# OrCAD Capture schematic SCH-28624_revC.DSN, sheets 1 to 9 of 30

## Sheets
1 19 XG-T PHY 2 Pwr: size B; title: T1024RDB; rev: C
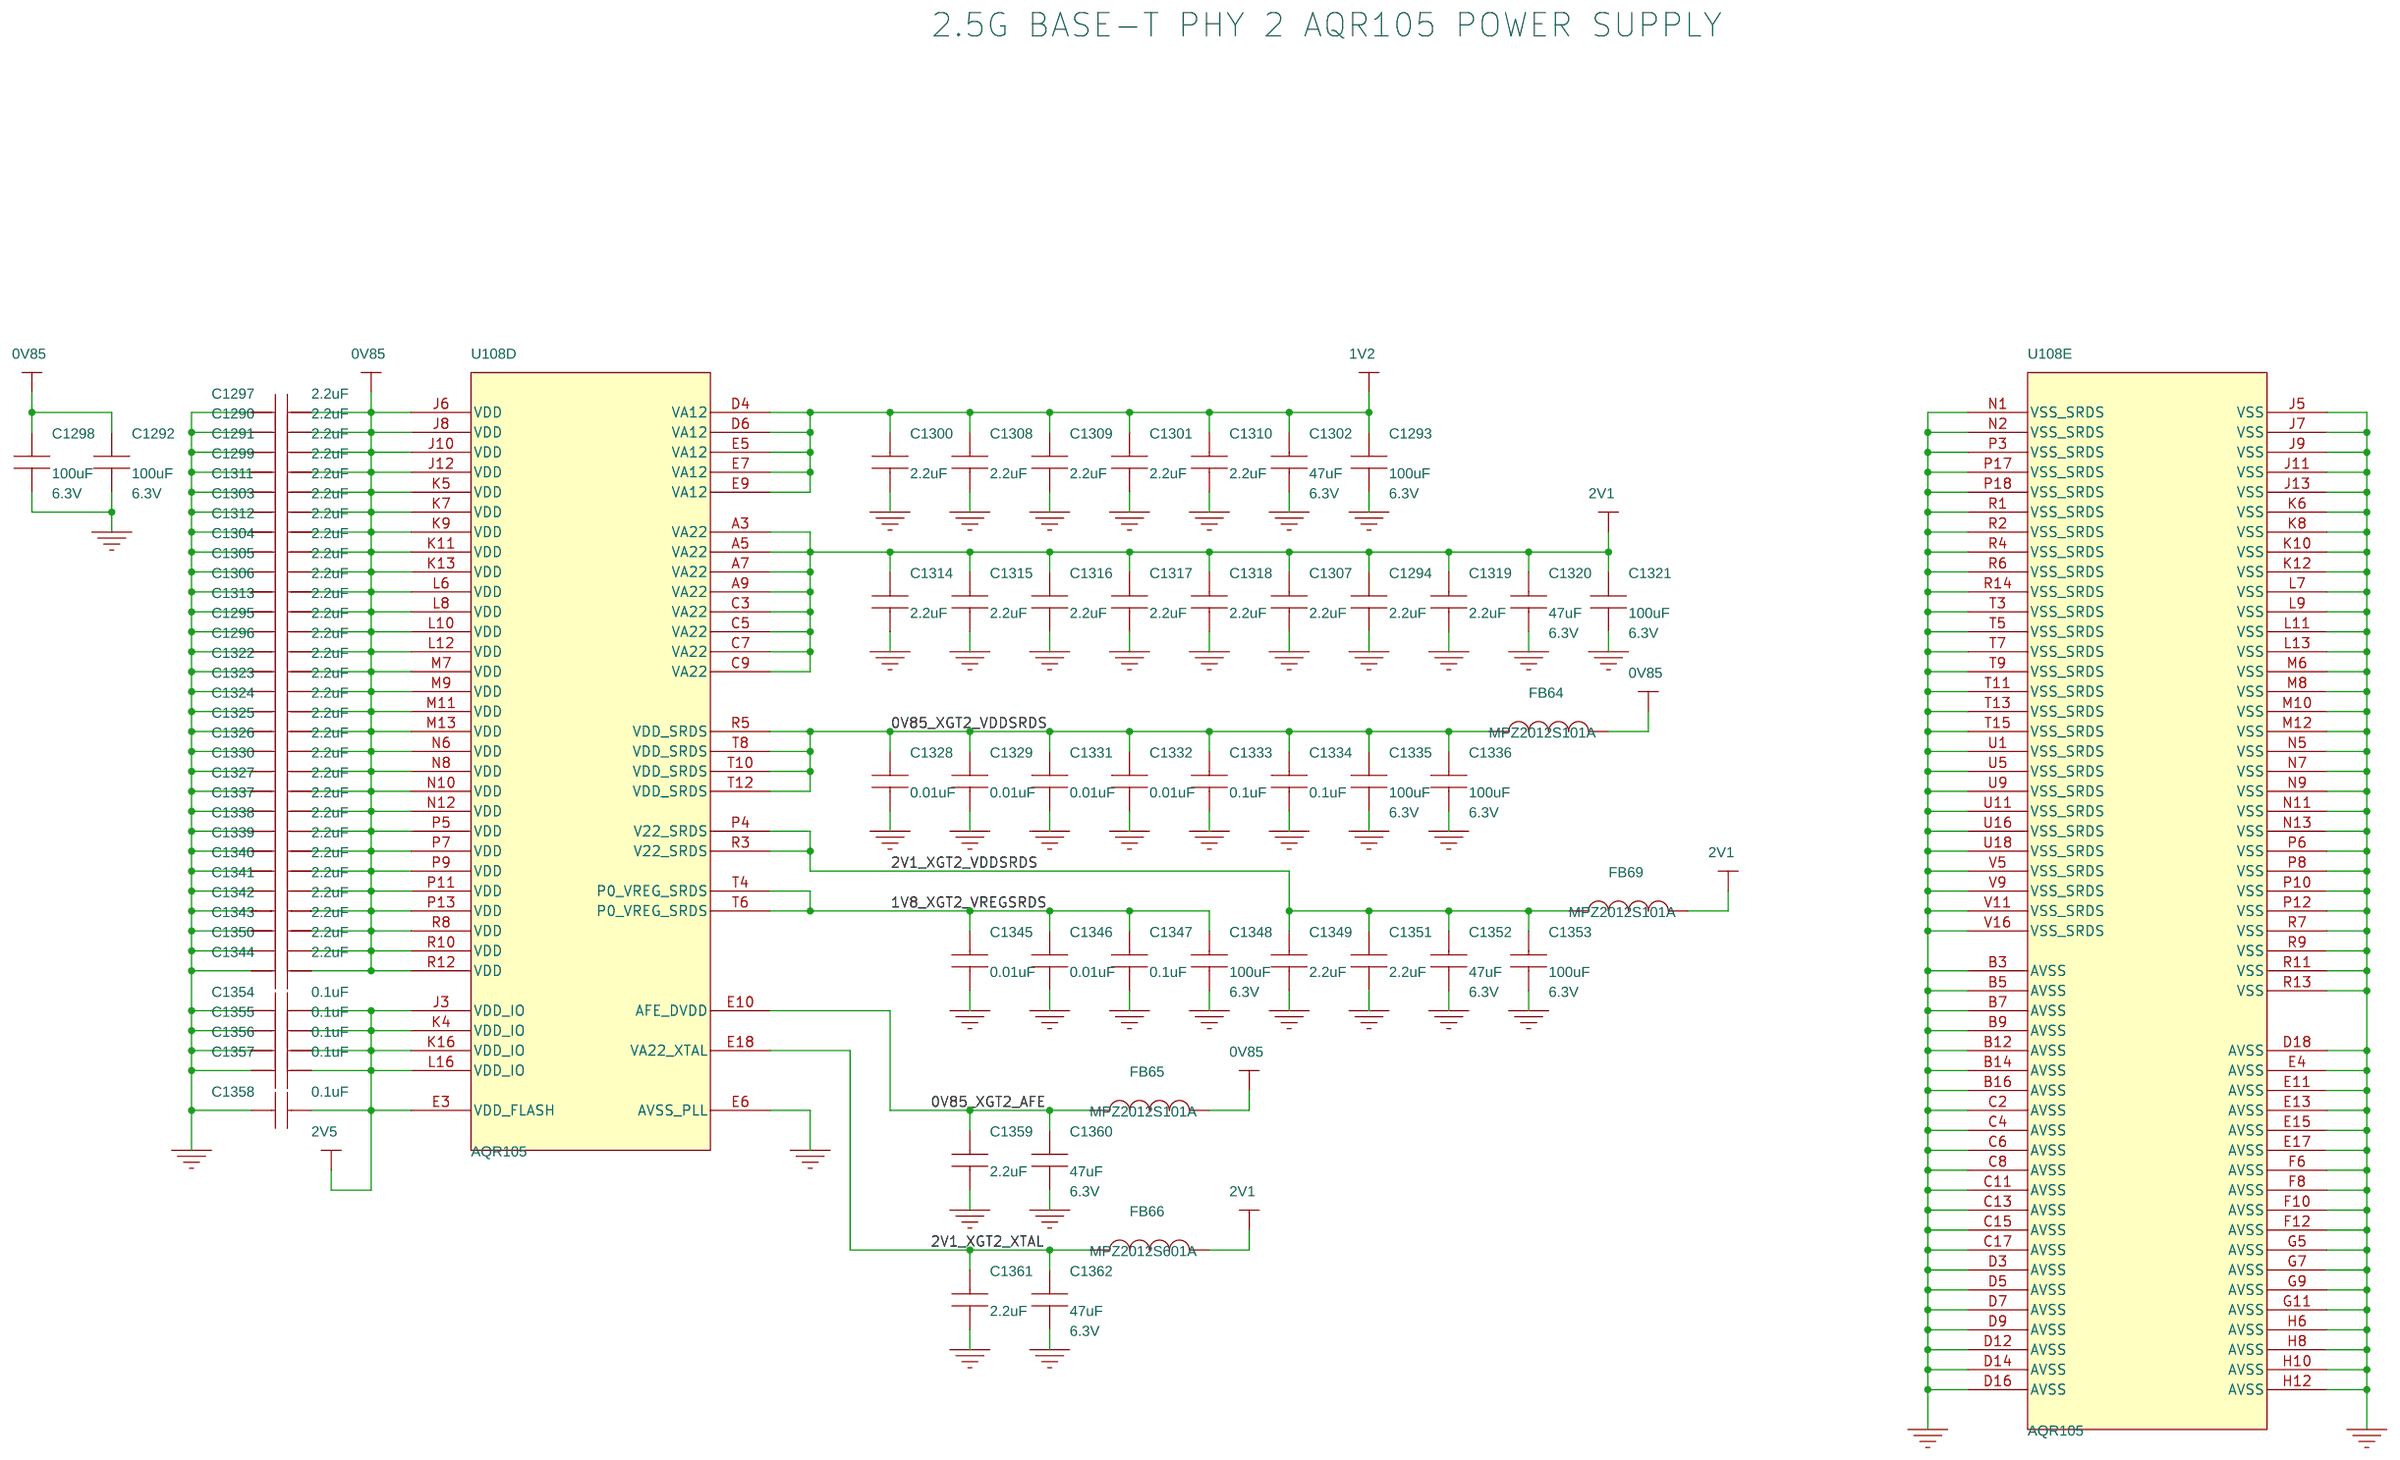
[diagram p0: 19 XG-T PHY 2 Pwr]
2 18 XG-T PHY 2: size B
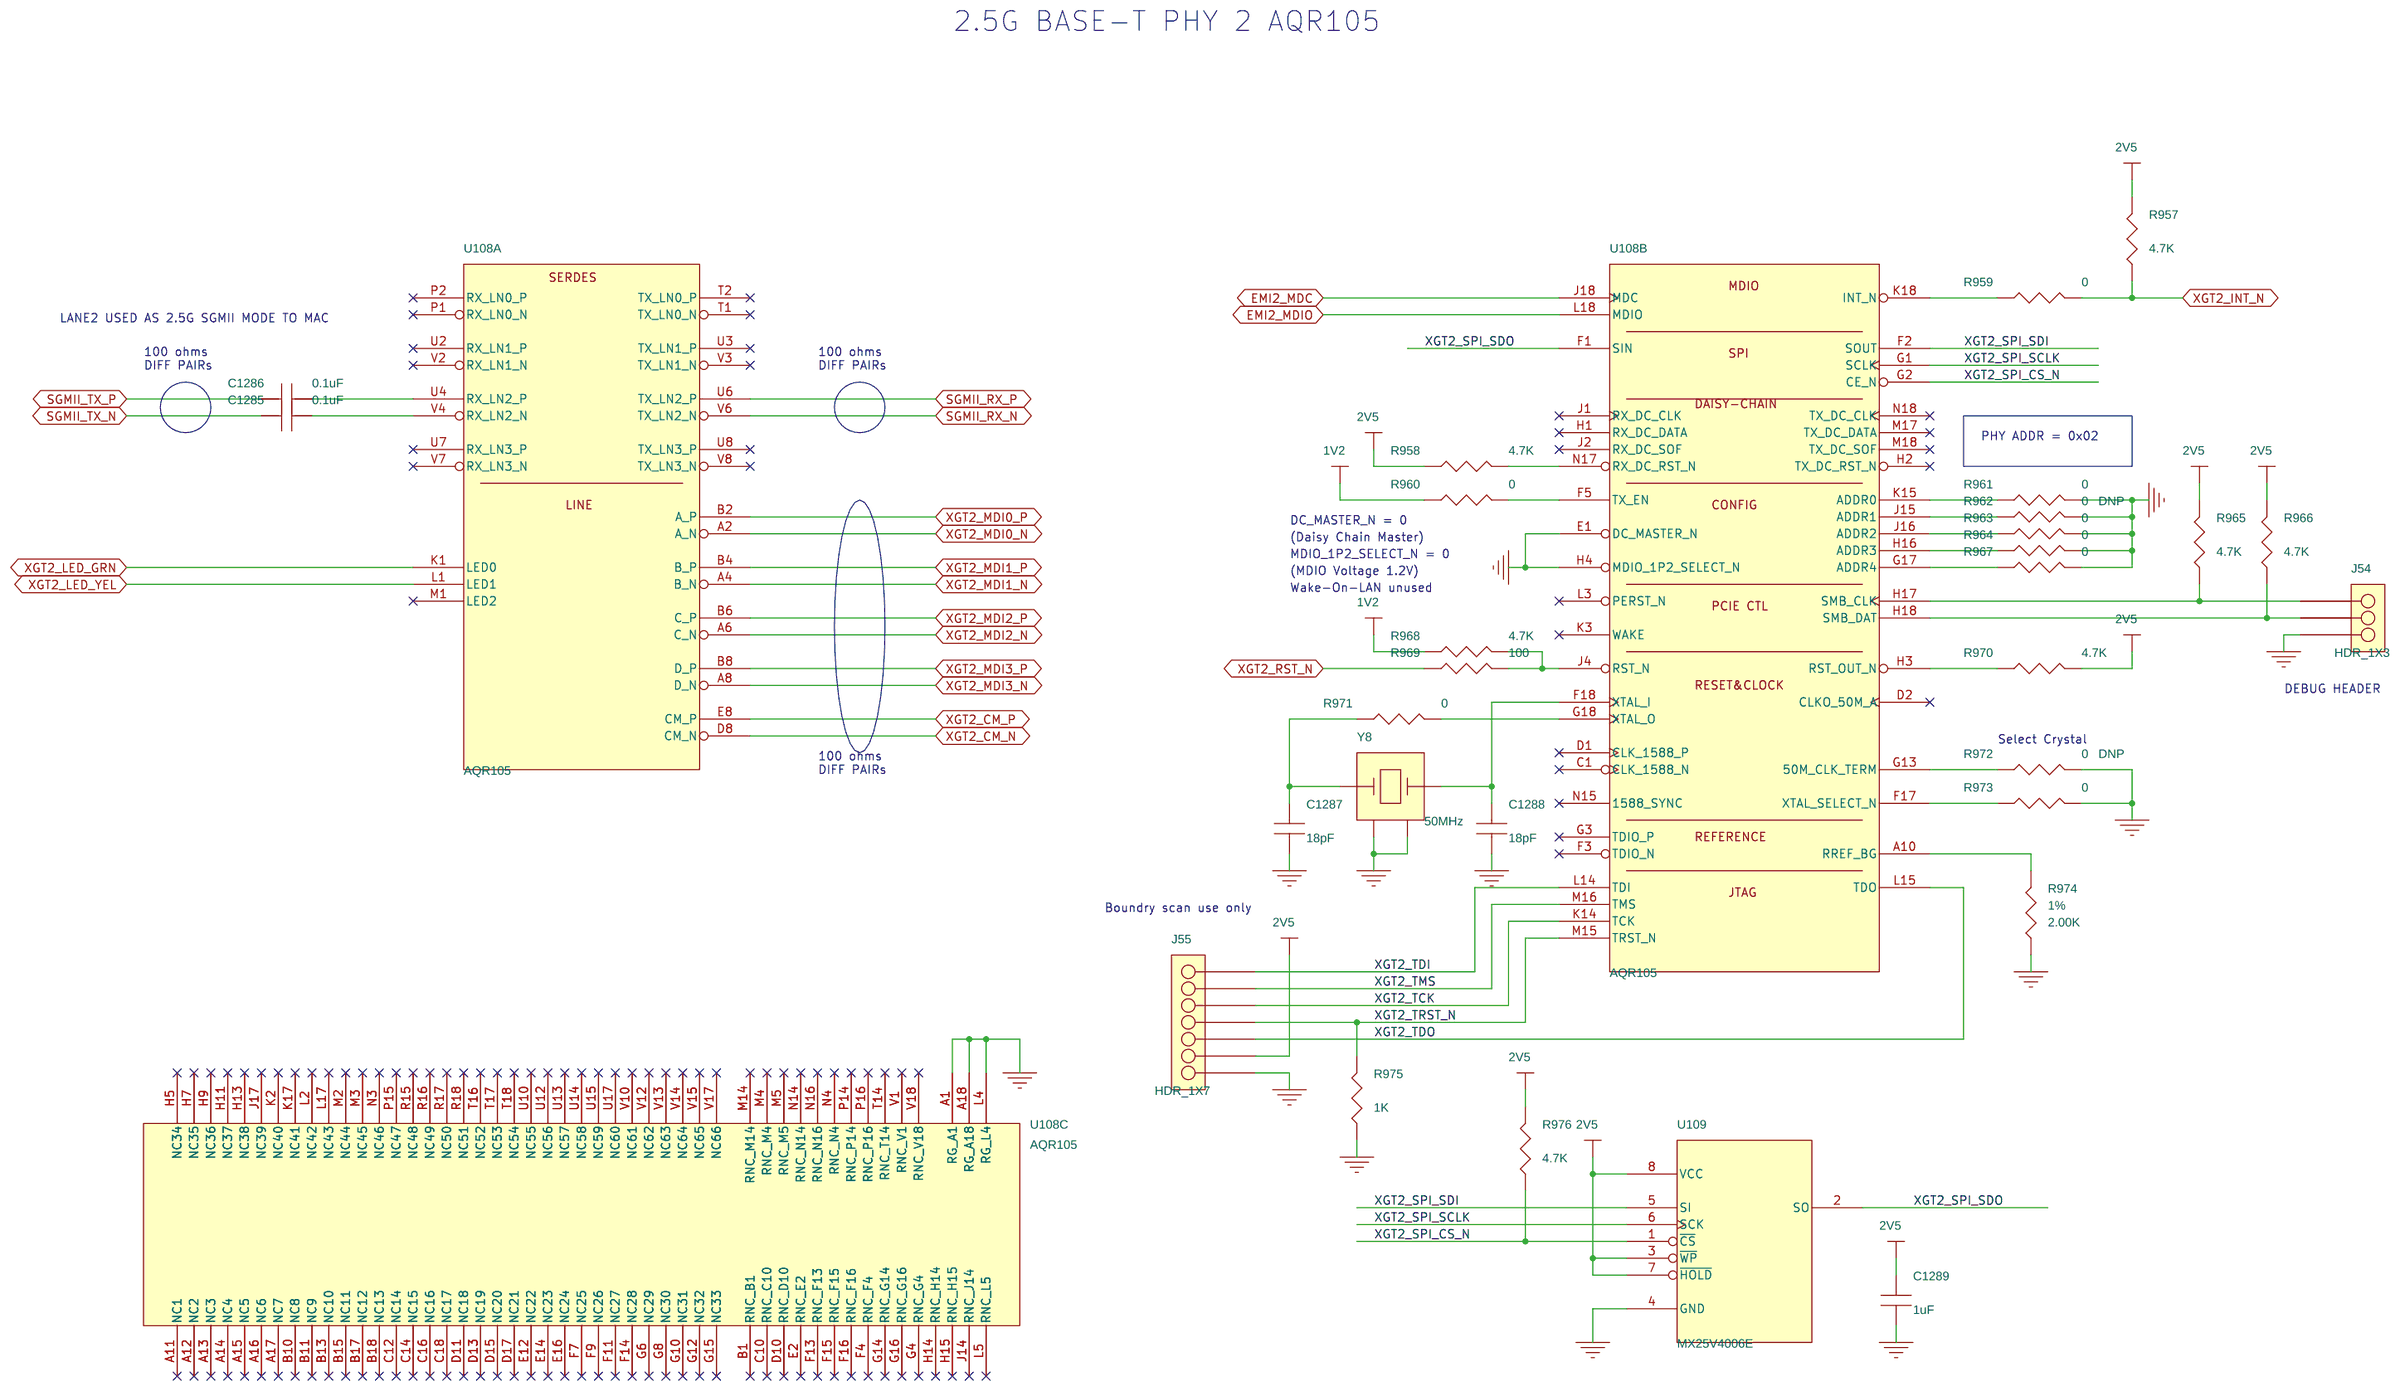
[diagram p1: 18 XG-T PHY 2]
3 01 Page Listing
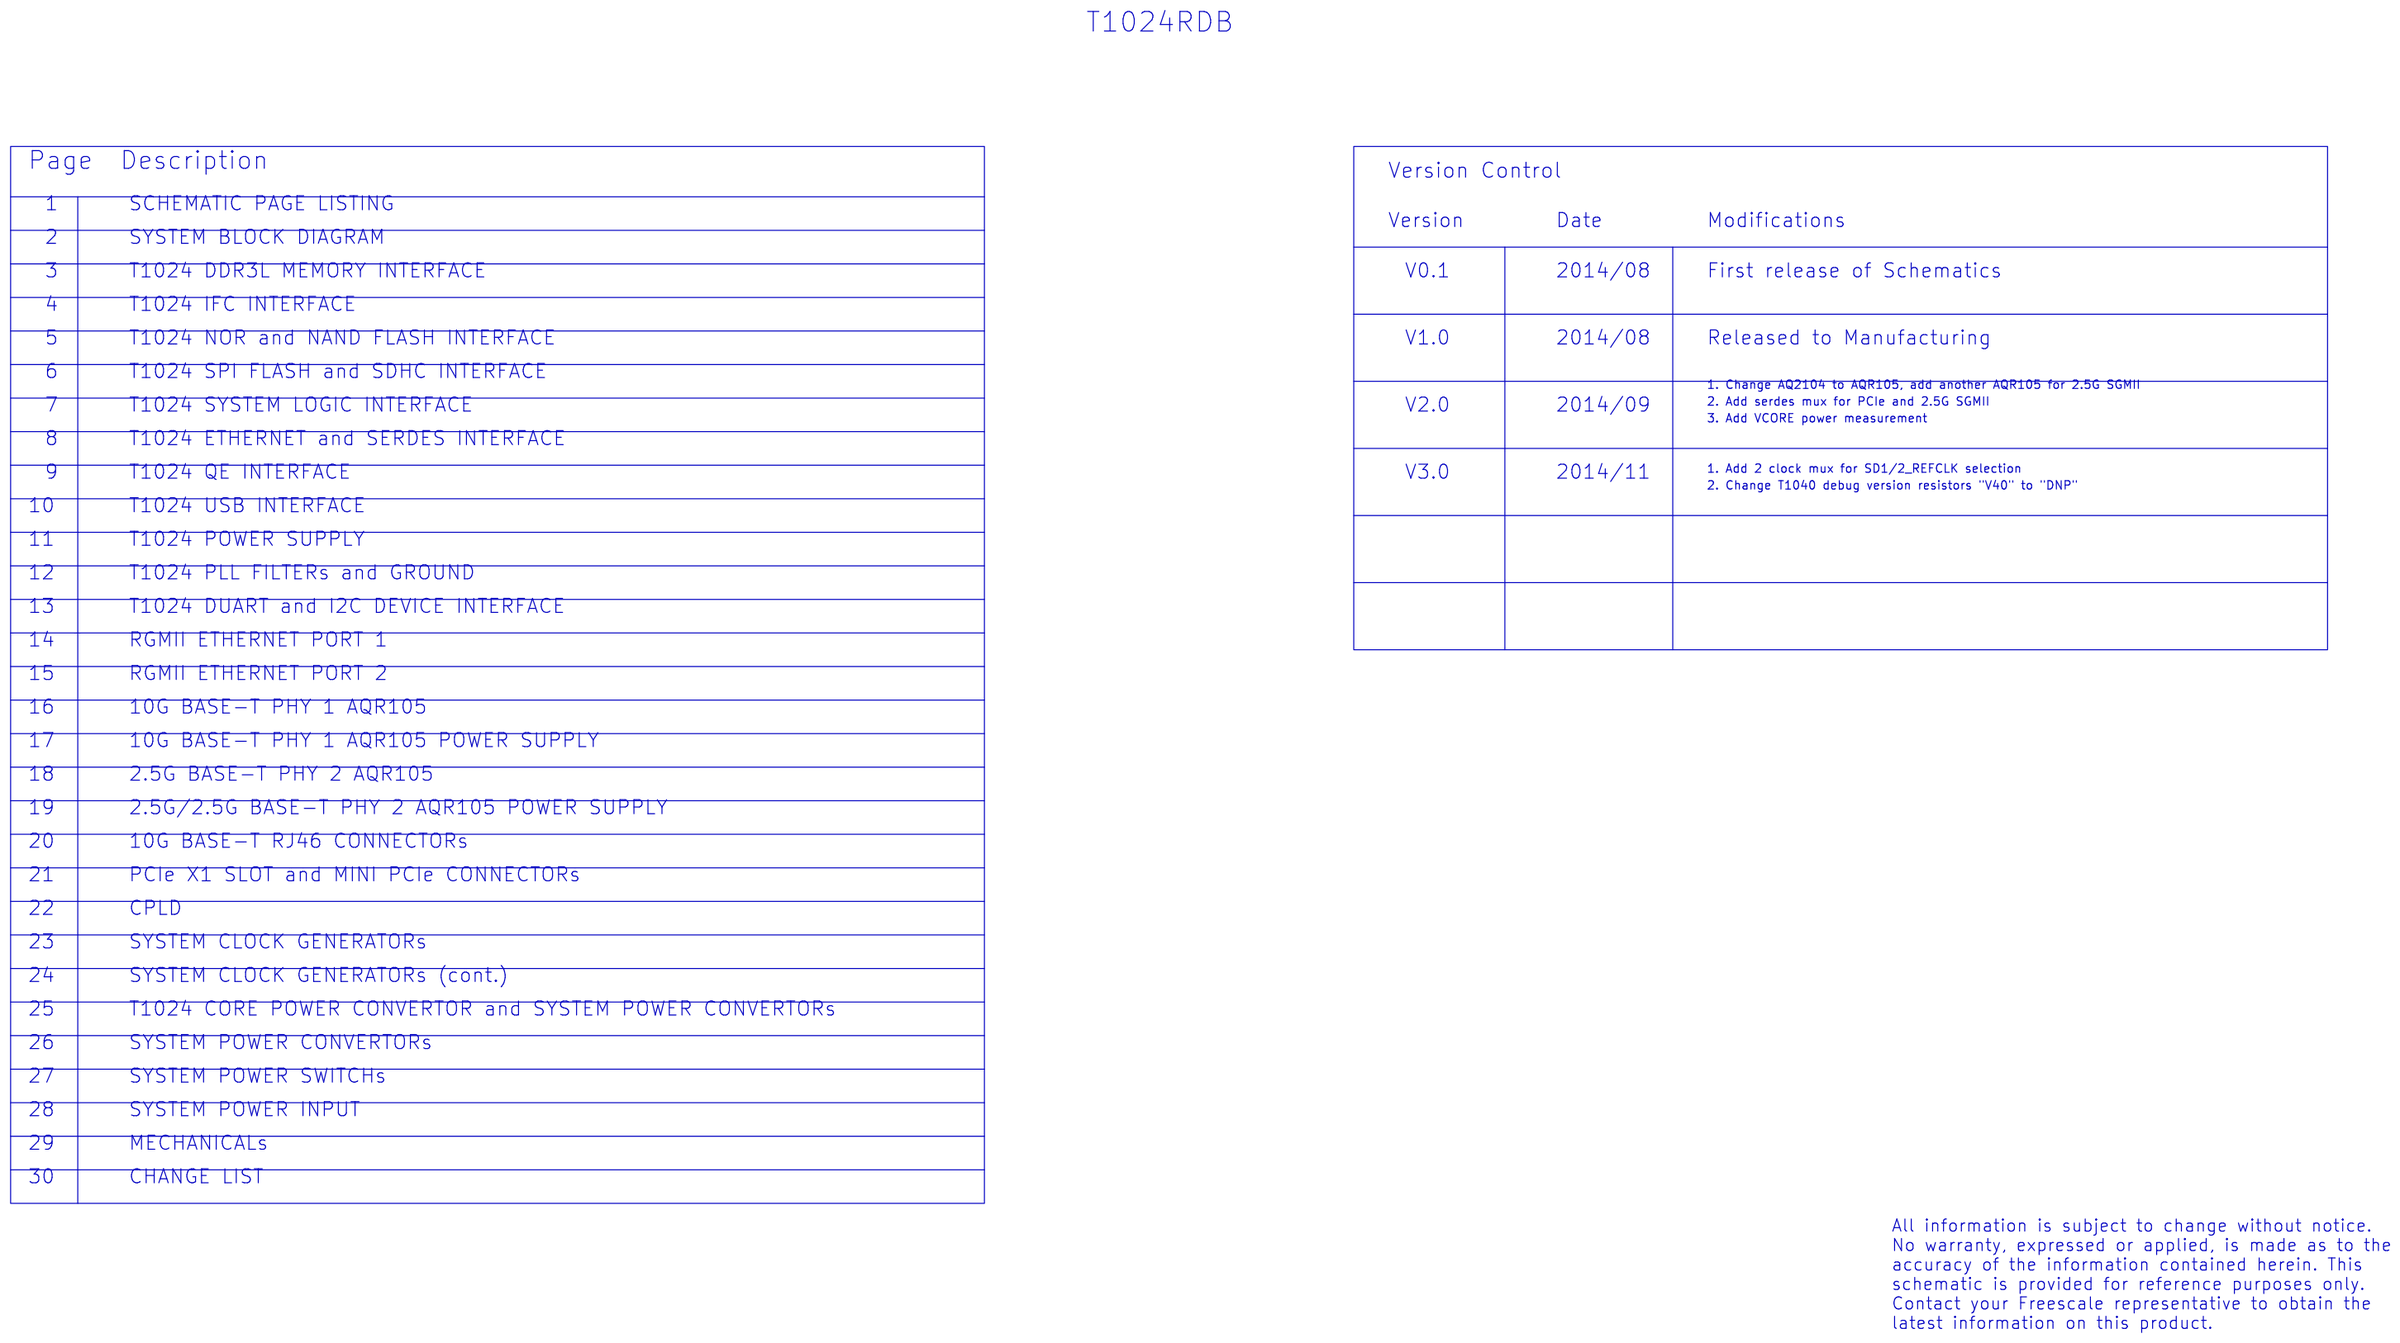
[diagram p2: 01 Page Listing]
4 02 Block Diagram
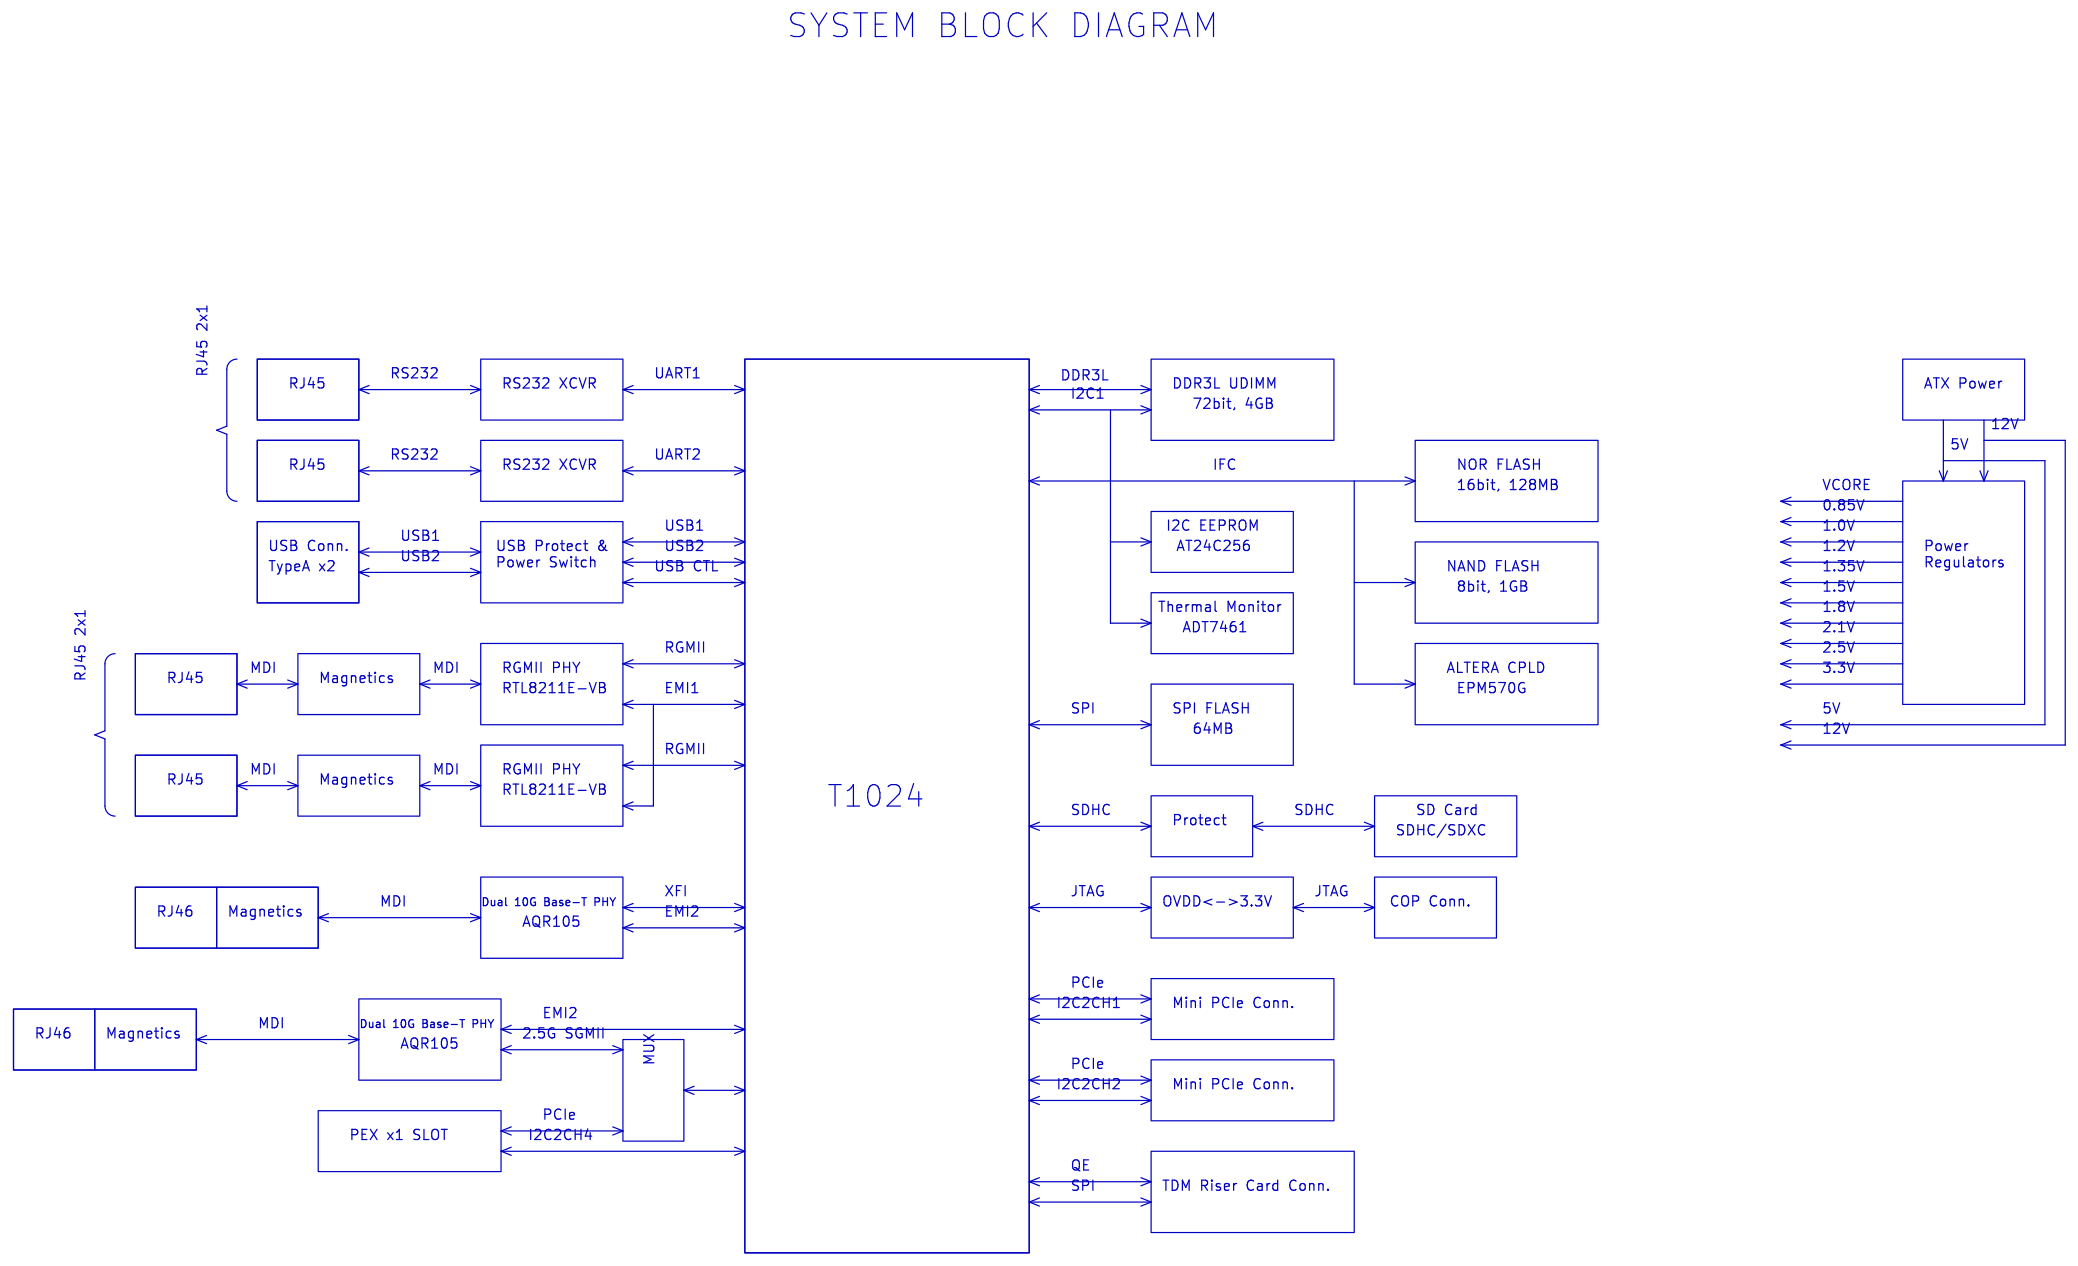
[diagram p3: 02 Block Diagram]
5 03 DDR3: size B
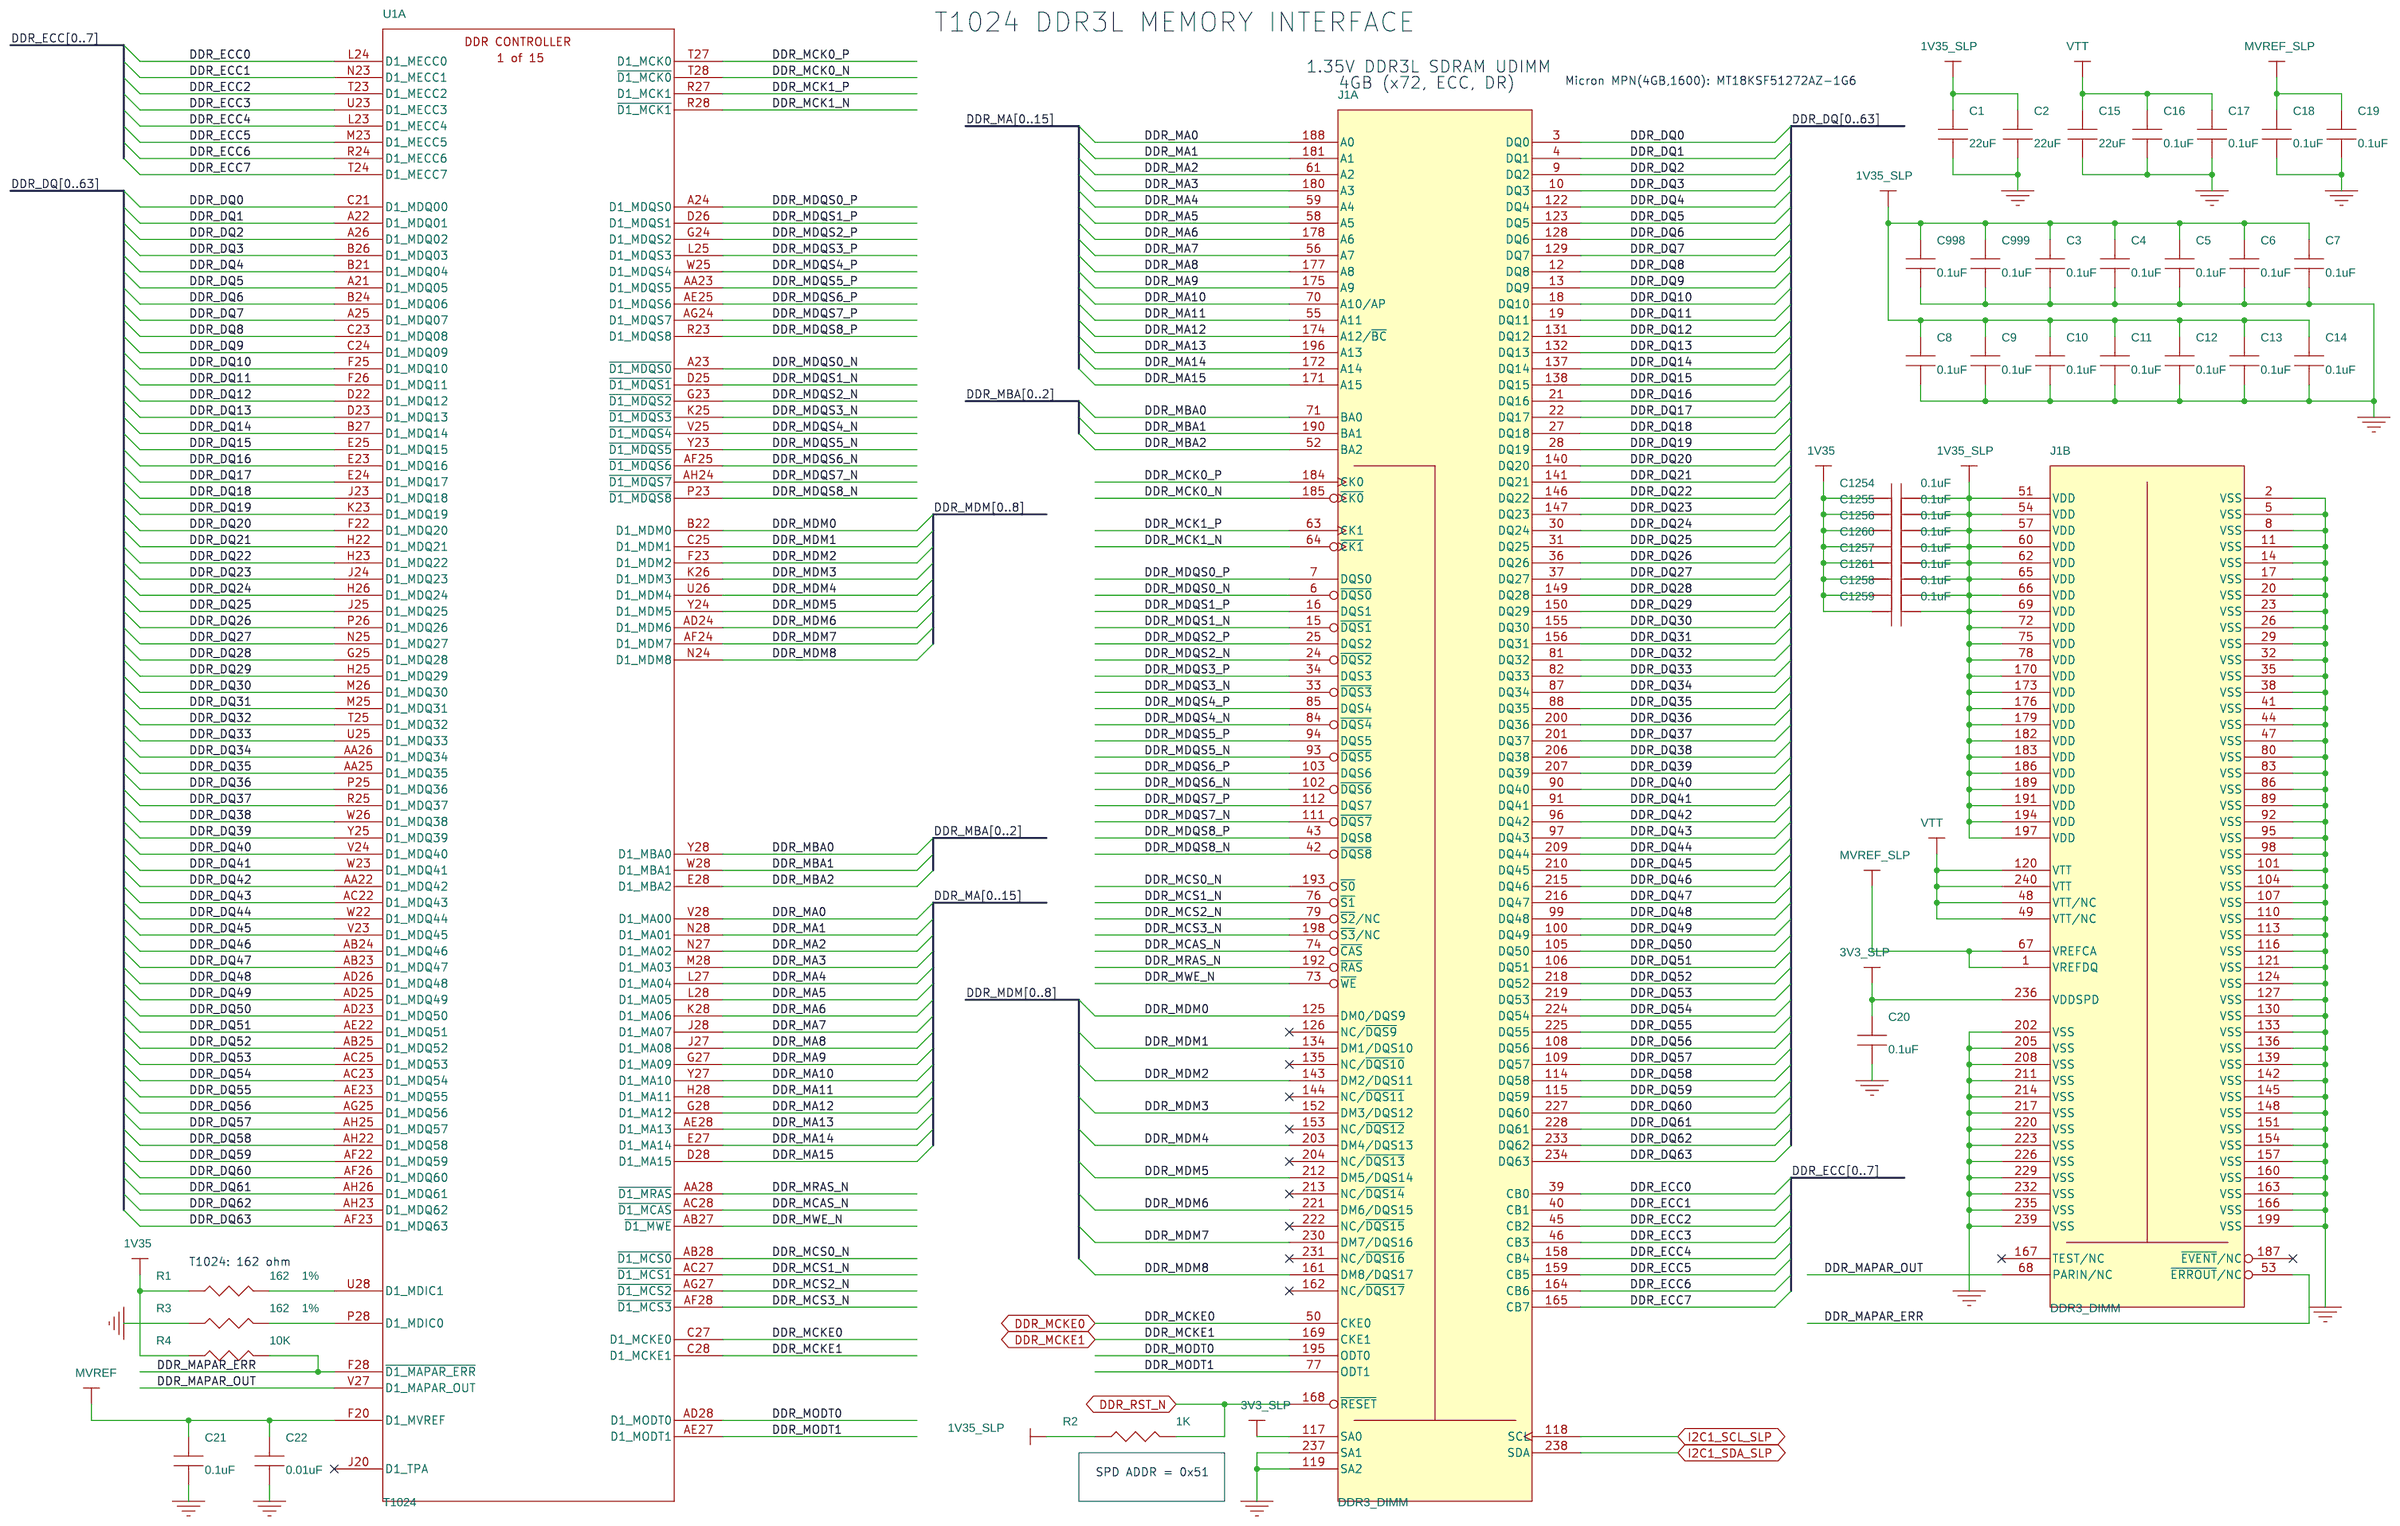
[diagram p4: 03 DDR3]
6 04 IFC: size B; rev: A
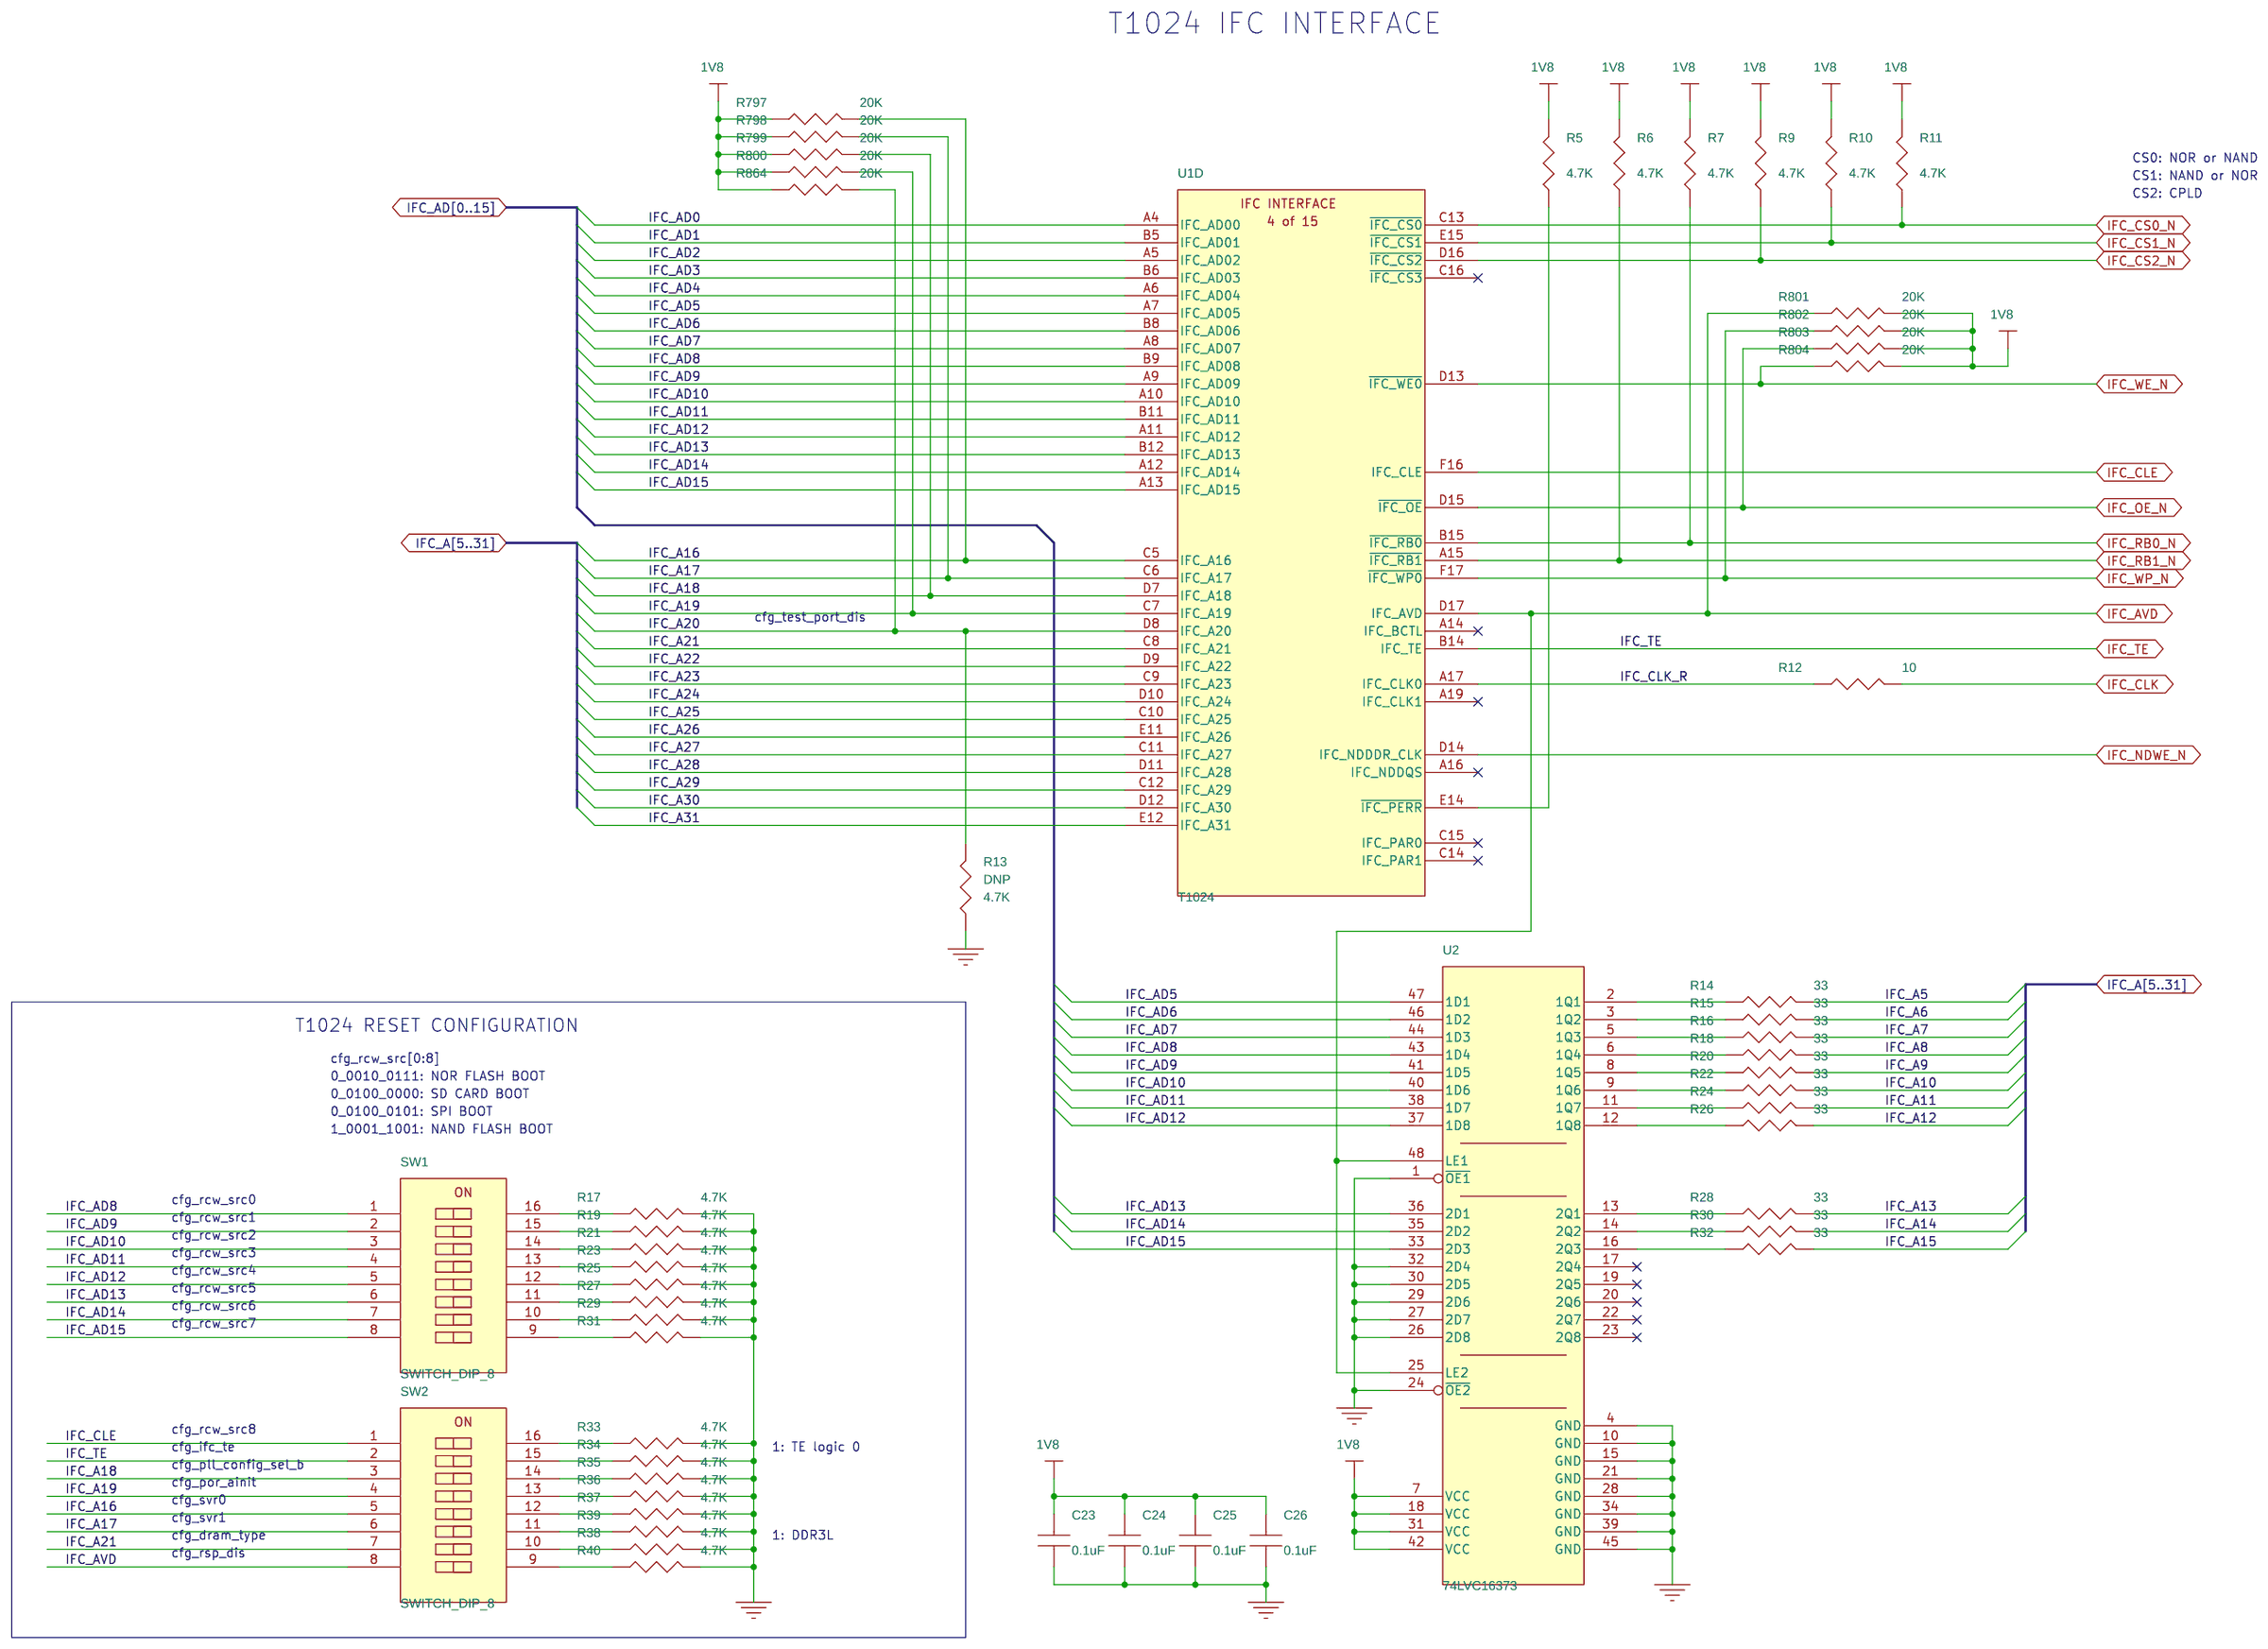
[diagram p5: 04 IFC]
7 05 Flash: size B
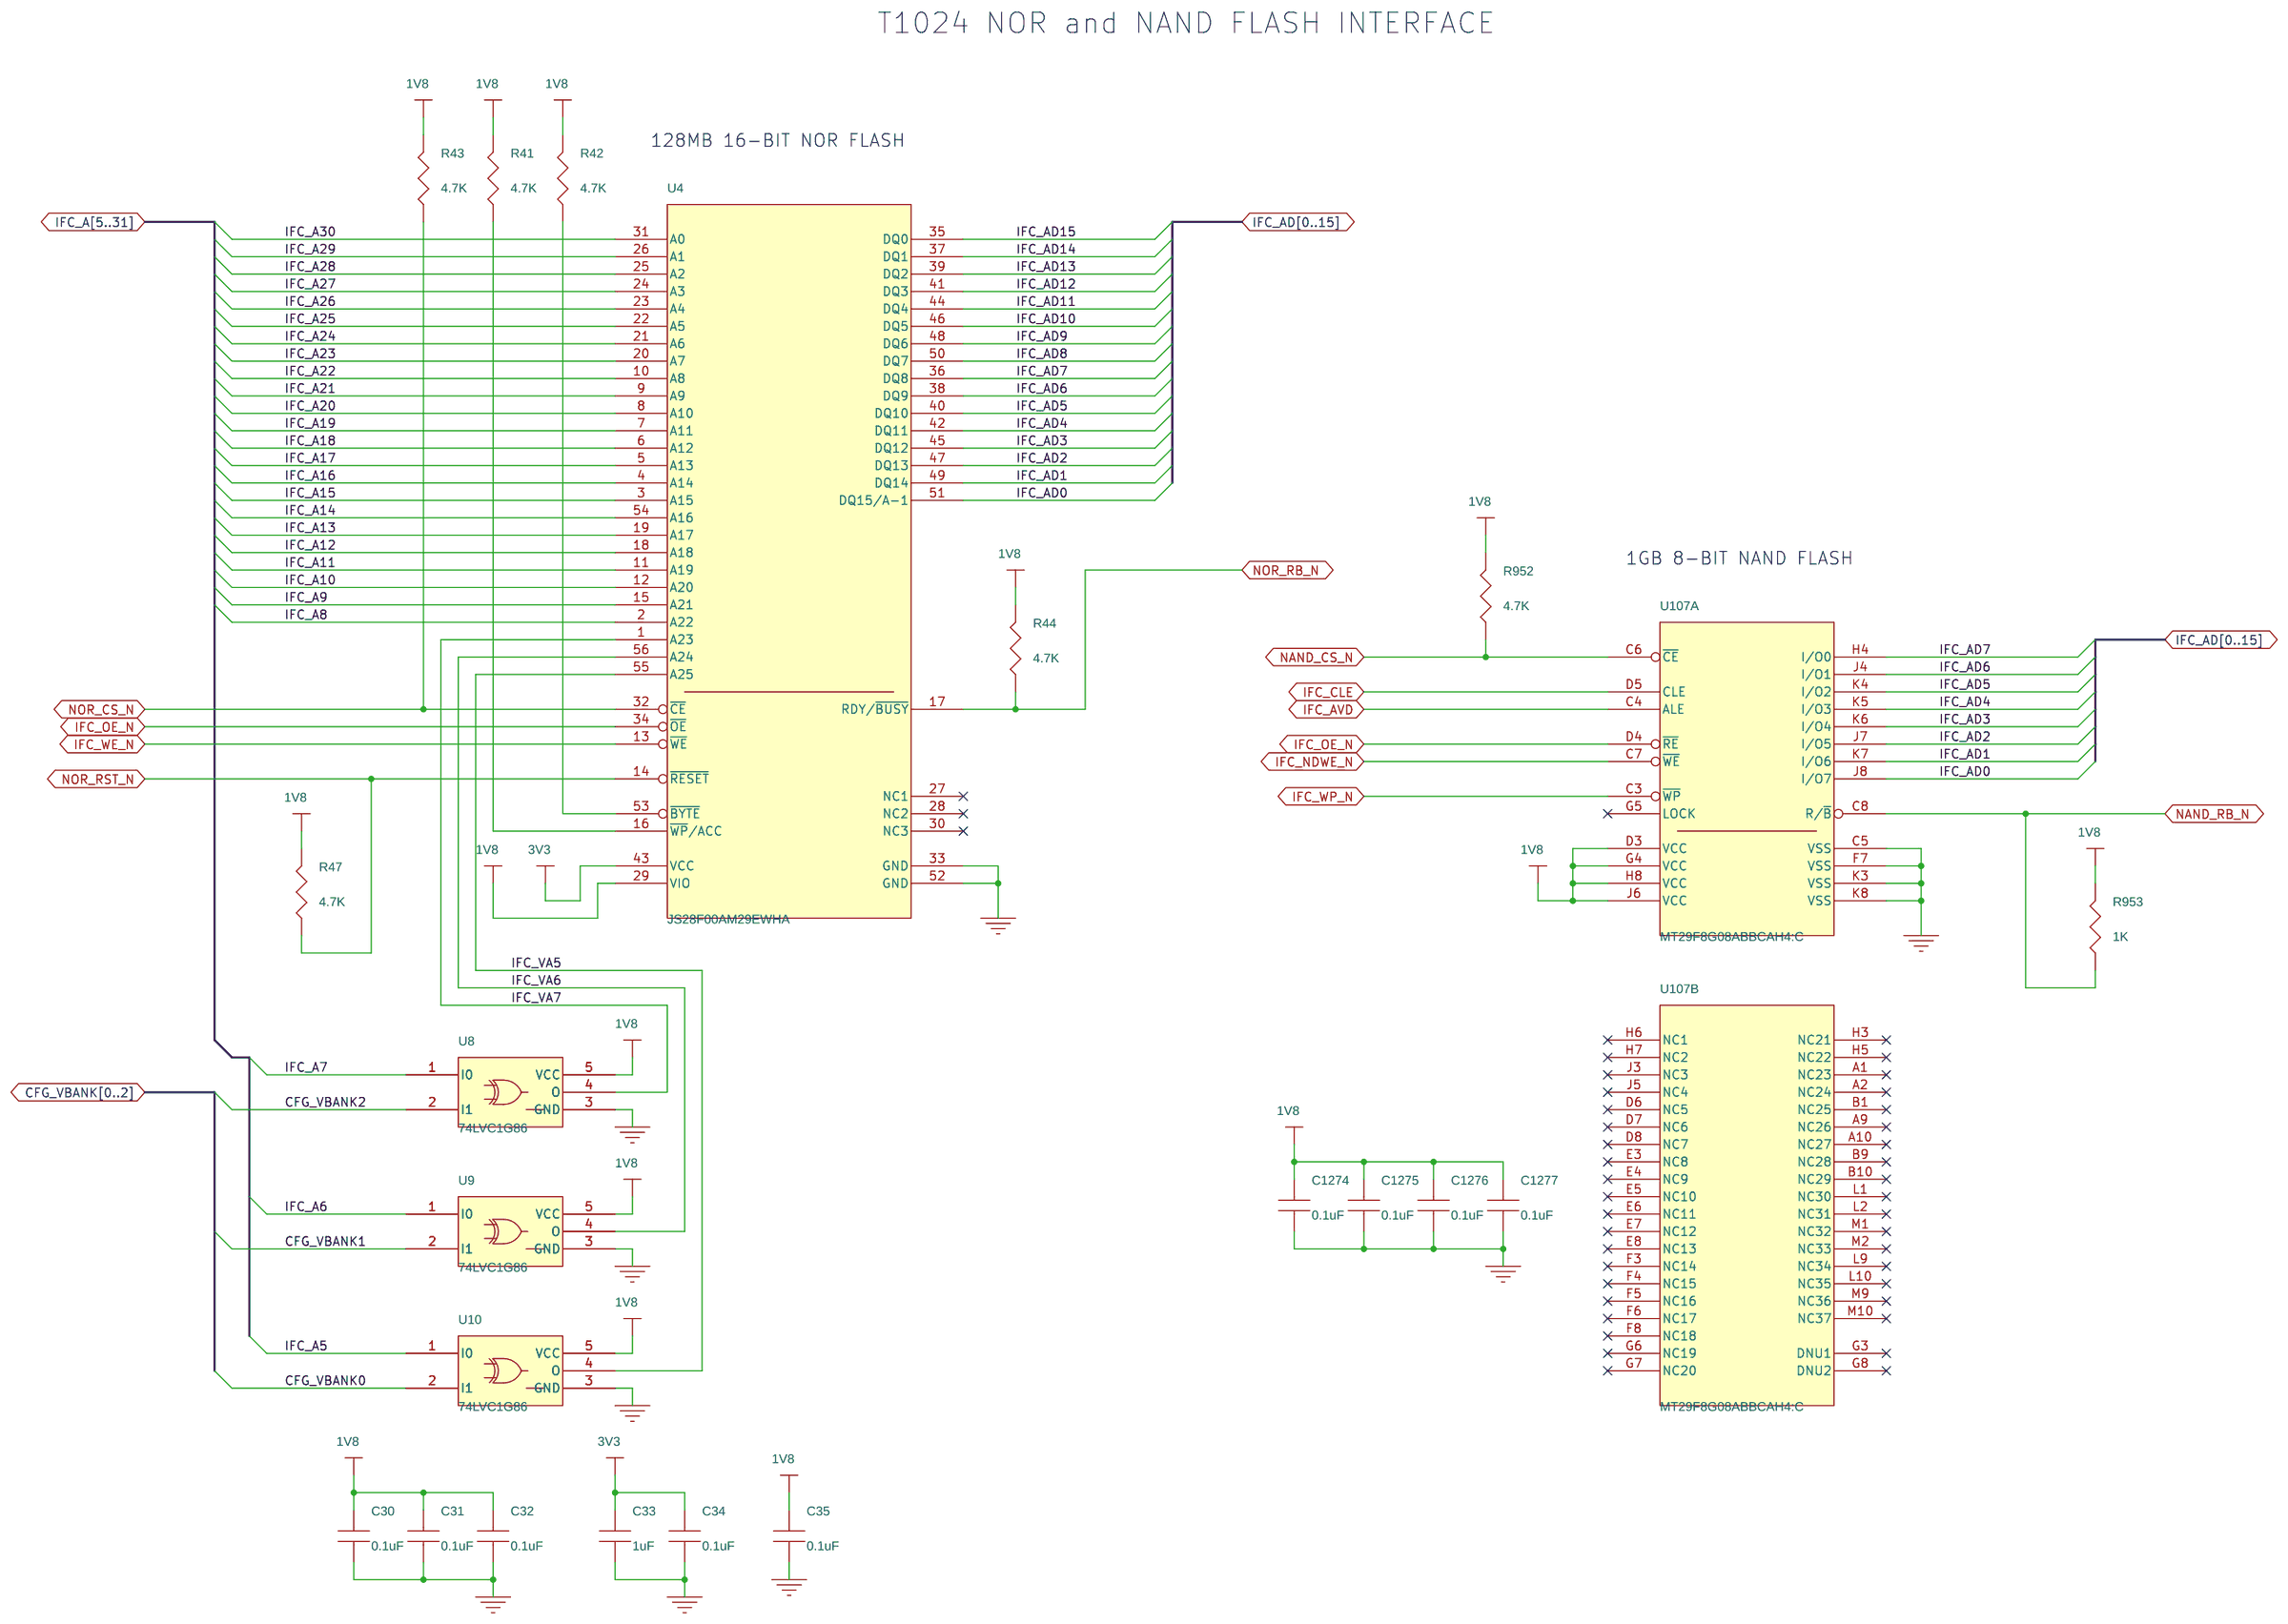
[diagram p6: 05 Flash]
8 06 SPI&SDHC: size B
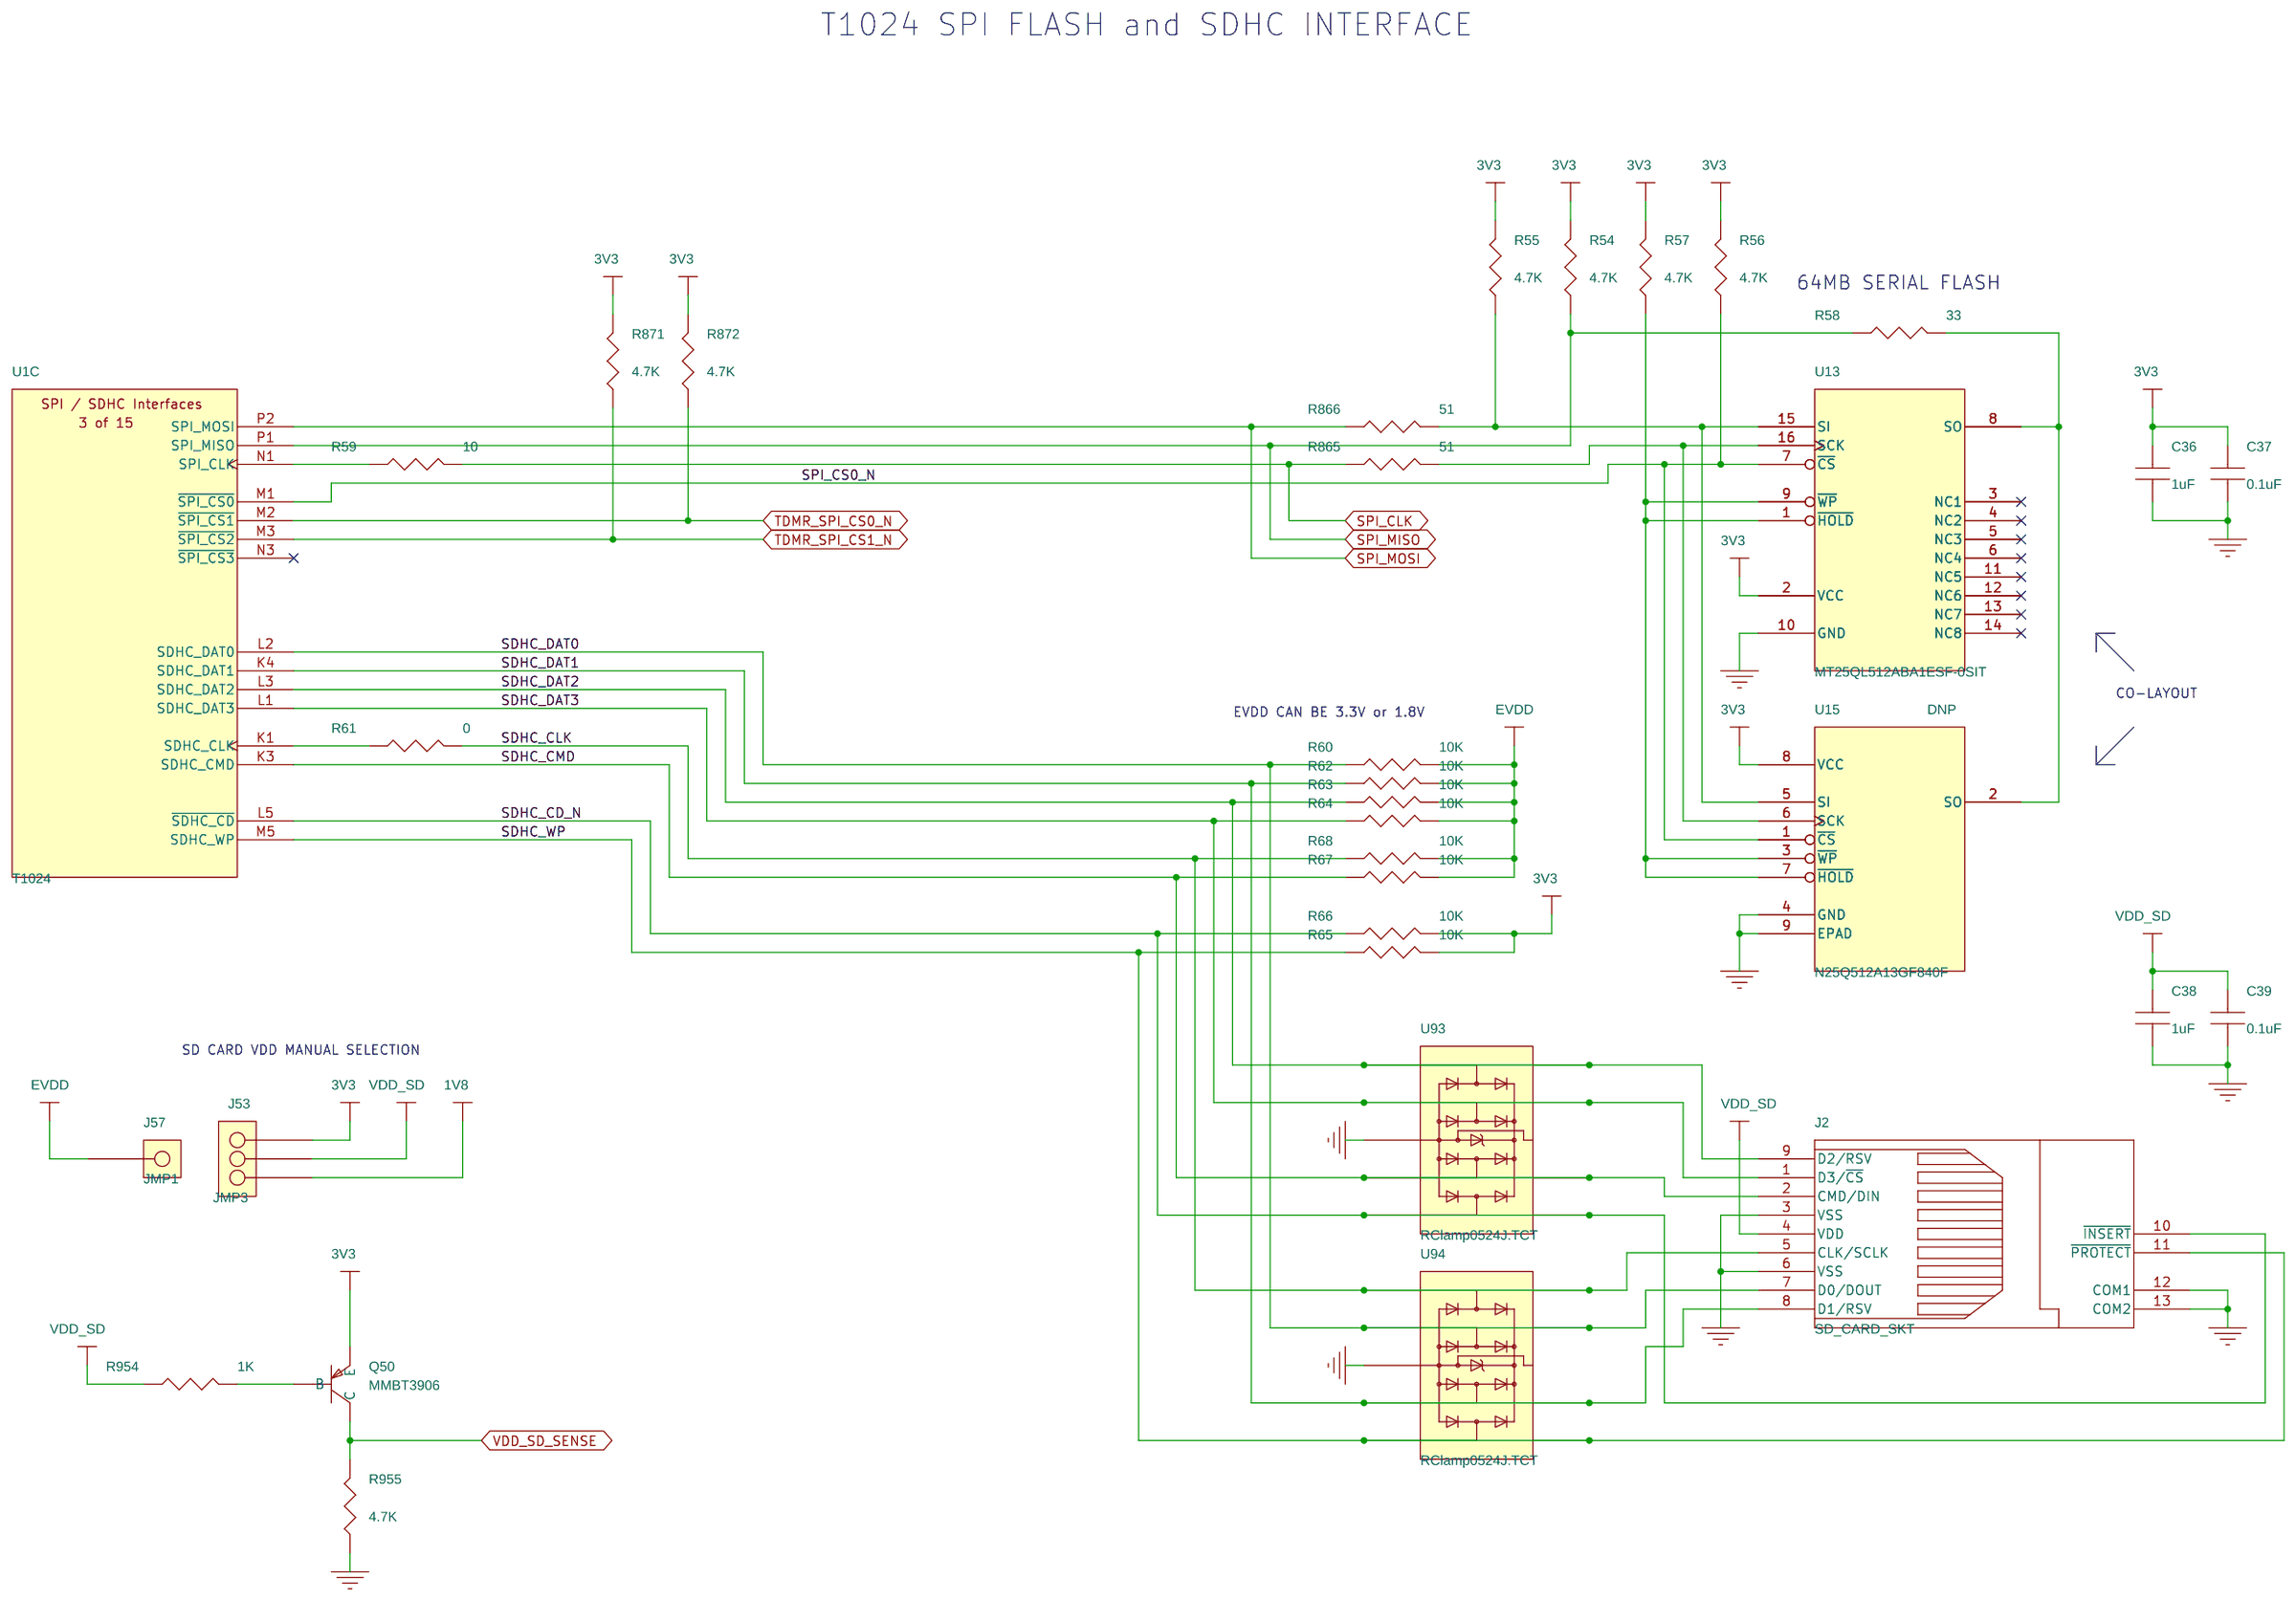
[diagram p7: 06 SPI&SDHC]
9 07 SYS: size B
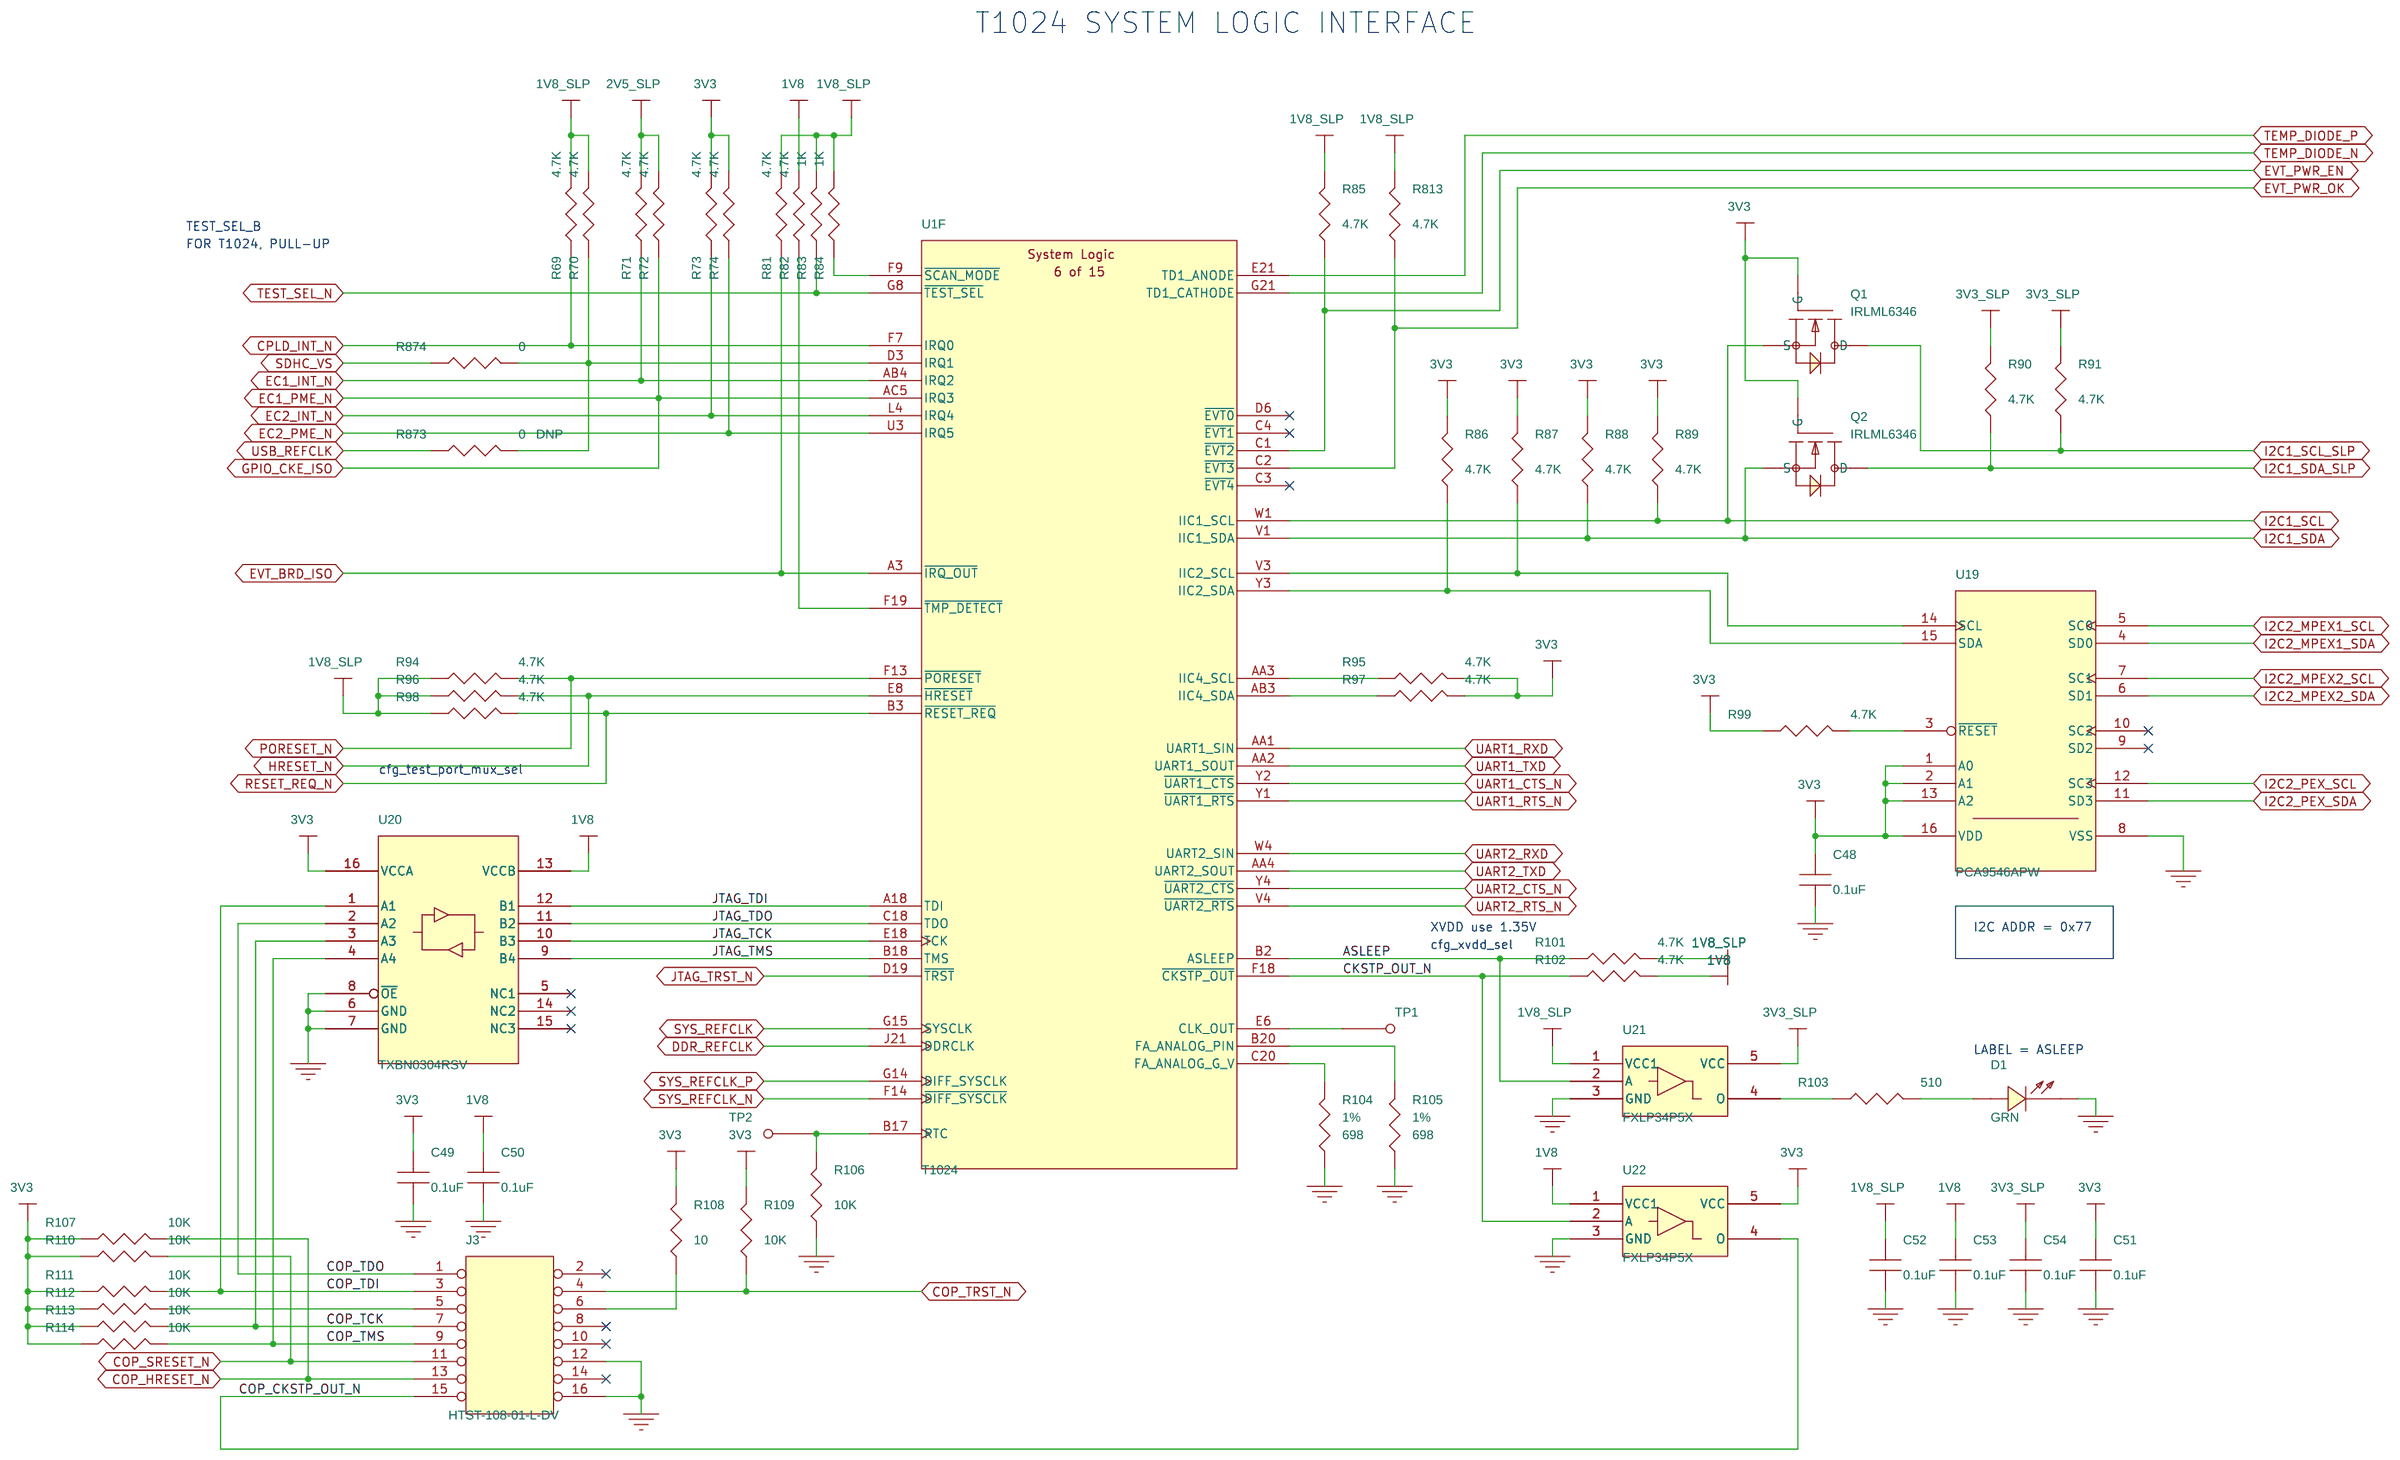
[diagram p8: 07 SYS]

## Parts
sheet 03 DDR3
C1  22uF  [0805]
C2  22uF  [0805]
C3  0.1uF  [0402]
C4  0.1uF  [0402]
C5  0.1uF  [0402]
C6  0.1uF  [0402]
C7  0.1uF  [0402]
C8  0.1uF  [0402]
C9  0.1uF  [0402]
C10  0.1uF  [0402]
C11  0.1uF  [0402]
C12  0.1uF  [0402]
C13  0.1uF  [0402]
C14  0.1uF  [0402]
C15  22uF  [0805]
C16  0.1uF  [0402]
C17  0.1uF  [0402]
C18  0.1uF  [0402]
C19  0.1uF  [0402]
C20  0.1uF  [0402]
C21  0.1uF  [0201]
C22  0.01uF  [0201]
C998  0.1uF  [0402]
C999  0.1uF  [0402]
C1254  0.1uF  [0402]
C1255  0.1uF  [0402]
C1256  0.1uF  [0402]
C1257  0.1uF  [0402]
C1258  0.1uF  [0402]
C1259  0.1uF  [0402]
C1260  0.1uF  [0402]
C1261  0.1uF  [0402]
J1  DDR3_DIMM  [con_ddr3_dimm]  (sections A,B)
R1  162  [0402]
R2  1K  [0402]
R3  162  [0402]
R4  10K  [0402]
U1  T1024  [bga_p080_780]  (sections A,B,C,D,E,F,G,H,I,J,K,L,M,N,O)
sheet 04 IFC
C23  0.1uF  [0402]
C24  0.1uF  [0402]
C25  0.1uF  [0402]
C26  0.1uF  [0402]
R5  4.7K  [0402]
R6  4.7K  [0402]
R7  4.7K  [0402]
R9  4.7K  [0402]
R10  4.7K  [0402]
R11  4.7K  [0402]
R12  10  [0402]
R13  4.7K  [0402]
R14  33  [0402]
R15  33  [0402]
R16  33  [0402]
R17  4.7K  [0402]
R18  33  [0402]
R19  4.7K  [0402]
R20  33  [0402]
R21  4.7K  [0402]
R22  33  [0402]
R23  4.7K  [0402]
R24  33  [0402]
R25  4.7K  [0402]
R26  33  [0402]
R27  4.7K  [0402]
R28  33  [0402]
R29  4.7K  [0402]
R30  33  [0402]
R31  4.7K  [0402]
R32  33  [0402]
R33  4.7K  [0402]
R34  4.7K  [0402]
R35  4.7K  [0402]
R36  4.7K  [0402]
R37  4.7K  [0402]
R38  4.7K  [0402]
R39  4.7K  [0402]
R40  4.7K  [0402]
R797  20K  [0402]
R798  20K  [0402]
R799  20K  [0402]
R800  20K  [0402]
R801  20K  [0402]
R802  20K  [0402]
R803  20K  [0402]
R804  20K  [0402]
R864  20K  [0402]
SW1  SWITCH_DIP_8  [con_switch_x8]
SW2  SWITCH_DIP_8  [con_switch_x8]
U2  74LVC16373  [tssop_48w]
sheet 05 Flash
C30  0.1uF  [0402]
C31  0.1uF  [0402]
C32  0.1uF  [0402]
C33  1uF  [0402]
C34  0.1uF  [0402]
C35  0.1uF  [0402]
C1274  0.1uF  [0402]
C1275  0.1uF  [0402]
C1276  0.1uF  [0402]
C1277  0.1uF  [0402]
R41  4.7K  [0402]
R42  4.7K  [0402]
R43  4.7K  [0402]
R44  4.7K  [0402]
R47  4.7K  [0402]
R952  4.7K  [0402]
R953  1K  [0402]
U4  JS28F00AM29EWHA  [tsop1_56]
U8  74LVC1G86  [sc70_5]
U9  74LVC1G86  [sc70_5]
U10  74LVC1G86  [sc70_5]
U107  MT29F8G08ABBCAH4:C  [bga_p080_nand_63]  (sections A,B)
sheet 06 SPI&SDHC
C36  1uF  [0402]
C37  0.1uF  [0402]
C38  1uF  [0402]
C39  0.1uF  [0402]
J2  SD_CARD_SKT  [con_sd]
J53  JMP3  [jmp_p254_t_1x3]
J57  JMP1  [jmp_p254_t_1x1]
Q50  MMBT3906  [sot23]
R54  4.7K  [0402]
R55  4.7K  [0402]
R56  4.7K  [0402]
R57  4.7K  [0402]
R58  33  [0402]
R59  10  [0402]
R60  10K  [0402]
R61  0  [0402]
R62  10K  [0402]
R63  10K  [0402]
R64  10K  [0402]
R65  10K  [0402]
R66  10K  [0402]
R67  10K  [0402]
R68  10K  [0402]
R865  51  [0402]
R866  51  [0402]
R871  4.7K  [0402]
R872  4.7K  [0402]
R954  1K  [0402]
R955  4.7K  [0402]
U13  MT25QL512ABA1ESF-0SIT  [so_16l]
U15  N25Q512A13GF840F  [wson_8]
U93  RClamp0524J.TCT  [tvs_slp2710p8]
U94  RClamp0524J.TCT  [tvs_slp2710p8]
sheet 07 SYS
C48  0.1uF  [0402]
C49  0.1uF  [0402]
C50  0.1uF  [0402]
C51  0.1uF  [0402]
C52  0.1uF  [0402]
C53  0.1uF  [0402]
C54  0.1uF  [0402]
D1  GRN  [led_0603]
J3  HTST-108-01-L-DV  [hdr_p254_htst_2x8]
Q1  IRLML6346  [sot23]
Q2  IRLML6346  [sot23]
R69  4.7K  [0402]
R70  4.7K  [0402]
R71  4.7K  [0402]
R72  4.7K  [0402]
R73  4.7K  [0402]
R74  4.7K  [0402]
R81  4.7K  [0402]
R82  4.7K  [0402]
R83  1K  [0402]
R84  1K  [0402]
R85  4.7K  [0402]
R86  4.7K  [0402]
R87  4.7K  [0402]
R88  4.7K  [0402]
R89  4.7K  [0402]
R90  4.7K  [0402]
R91  4.7K  [0402]
R94  4.7K  [0402]
R95  4.7K  [0402]
R96  4.7K  [0402]
R97  4.7K  [0402]
R98  4.7K  [0402]
R99  4.7K  [0402]
R101  4.7K  [0402]
R102  4.7K  [0402]
R103  510  [0402]
R104  698  [0402]
R105  698  [0402]
R106  10K  [0402]
R107  10K  [0402]
R108  10  [0402]
R109  10K  [0402]
R110  10K  [0402]
R111  10K  [0402]
R112  10K  [0402]
R113  10K  [0402]
R114  10K  [0402]
R813  4.7K  [0402]
R873  0  [0402]
R874  0  [0402]
TP1  TP  [tp]
TP2  TP  [tp]
U19  PCA9546APW  [tssop_16]
U20  TXBN0304RSV  [qfn_p040_d040_b260x180_16]
U21  FXLP34P5X  [sc70_5]
U22  FXLP34P5X  [sc70_5]
sheet 18 XG-T PHY 2
C1285  0.1uF  [0402]
C1286  0.1uF  [0402]
C1287  18pF  [0402]
C1288  18pF  [0402]
C1289  1uF  [0402]
J54  HDR_1X3  [hdr_p254_m_t_1x3]
J55  HDR_1X7  [hdr_p254_m_t_1x7]
R957  4.7K  [0402]
R958  4.7K  [0402]
R959  0  [0402]
R960  0  [0402]
R961  0  [0402]
R962  0  [0402]
R963  0  [0402]
R964  0  [0402]
R965  4.7K  [0402]
R966  4.7K  [0402]
R967  0  [0402]
R968  4.7K  [0402]
R969  100  [0402]
R970  4.7K  [0402]
R971  0  [0402]
R972  0  [0402]
R973  0  [0402]
R974  2.00K  [0402]
R975  1K  [0402]
R976  4.7K  [0402]
U108  AQR105  [bga_p100_324]  (sections A,B,C,D,E)
U109  MX25V4006E  [so_8]
Y8  50MHz  [cry_32x25_4]
sheet 19 XG-T PHY 2 Pwr
C1290  2.2uF  [0402]
C1291  2.2uF  [0402]
C1292  100uF  [1206]
C1293  100uF  [1206]
C1294  2.2uF  [0402]
C1295  2.2uF  [0402]
C1296  2.2uF  [0402]
C1297  2.2uF  [0402]
C1298  100uF  [1206]
C1299  2.2uF  [0402]
C1300  2.2uF  [0402]
C1301  2.2uF  [0402]
C1302  47uF  [0805]
C1303  2.2uF  [0402]
C1304  2.2uF  [0402]
C1305  2.2uF  [0402]
C1306  2.2uF  [0402]
C1307  2.2uF  [0402]
C1308  2.2uF  [0402]
C1309  2.2uF  [0402]
C1310  2.2uF  [0402]
C1311  2.2uF  [0402]
C1312  2.2uF  [0402]
C1313  2.2uF  [0402]
C1314  2.2uF  [0402]
C1315  2.2uF  [0402]
C1316  2.2uF  [0402]
C1317  2.2uF  [0402]
C1318  2.2uF  [0402]
C1319  2.2uF  [0402]
C1320  47uF  [0805]
C1321  100uF  [1206]
C1322  2.2uF  [0402]
C1323  2.2uF  [0402]
C1324  2.2uF  [0402]
C1325  2.2uF  [0402]
C1326  2.2uF  [0402]
C1327  2.2uF  [0402]
C1328  0.01uF  [0402]
C1329  0.01uF  [0402]
C1330  2.2uF  [0402]
C1331  0.01uF  [0402]
C1332  0.01uF  [0402]
C1333  0.1uF  [0402]
C1334  0.1uF  [0402]
C1335  100uF  [1206]
C1336  100uF  [1206]
C1337  2.2uF  [0402]
C1338  2.2uF  [0402]
C1339  2.2uF  [0402]
C1340  2.2uF  [0402]
C1341  2.2uF  [0402]
C1342  2.2uF  [0402]
C1343  2.2uF  [0402]
C1344  2.2uF  [0402]
C1345  0.01uF  [0402]
C1346  0.01uF  [0402]
C1347  0.1uF  [0402]
C1348  100uF  [1206]
C1349  2.2uF  [0402]
C1350  2.2uF  [0402]
C1351  2.2uF  [0402]
C1352  47uF  [0805]
C1353  100uF  [1206]
C1354  0.1uF  [0402]
C1355  0.1uF  [0402]
C1356  0.1uF  [0402]
C1357  0.1uF  [0402]
C1358  0.1uF  [0402]
C1359  2.2uF  [0402]
C1360  47uF  [0805]
C1361  2.2uF  [0402]
C1362  47uF  [0805]
FB64  MPZ2012S101A  [0805]
FB65  MPZ2012S101A  [0805]
FB66  MPZ2012S601A  [0805]
FB69  MPZ2012S101A  [0805]

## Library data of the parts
C1 C2 C15 = CAP: AGILE_PN: 150-30121; VOLTAGE: 6.3V
C3-C14 C16-C20 C23-C26 C30-C32 C34 C35 C37 C39 C48-C54 C998 C999 C1254-C1261 C1274-C1277 C1285 C1286 C1333 C1334 C1347 C1354-C1358 = CAP: AGILE_PN: 150-75663; VOLTAGE: 16V
C21 C33 C36 C38 C1289 = CAP: AGILE_PN: 150-75421; VOLTAGE: 6.3V
C22 = CAP: AGILE_PN: 150-75465; VOLTAGE: 10V
J1 = DDR3_DIMM: AGILE_PN: 210-00064; MPN: 78079-0053; TYPE: CON; Vendor: MOLEX
R1 R3 = RES: AGILE_PN: 470-30769; TOL: 1%
R2 R83 R84 R953 R954 R975 = RES: AGILE_PN: 470-75555; TOL: 5%
R4 R60 R62-R68 R106 R107 R109-R114 = RES: AGILE_PN: 470-75557; TOL: 5%
U1 = T1024: AGILE_PN: 312-00102; TYPE: IC; Vendor: Freescale
R5-R7 R9-R11 R17 R19 R21 R23 R25 R27 R29 R31 R33-R44 R47 R54-R57 R69-R74 R81 R82 R85-R91 R94-R99 R101 R102 R813 R871 R872 R952 R955 R957 R958 R965 R966 R968 R970 R976 = RES: AGILE_PN: 470-75626; TOL: 5%
R12 R59 R108 = RES: AGILE_PN: 470-75589; TOL: 5%
R13 R873 R962 R972 = RES: BOM_IGNORE: DNP; TOL: 5%
R14-R16 R18 R20 R22 R24 R26 R28 R30 R32 R58 = RES: AGILE_PN: 470-75790; TOL: 5%
R797-R804 R864 = RES: AGILE_PN: 470-76086; TOL: 5%
SW1 SW2 = SWITCH_DIP_8: AGILE_PN: 510-77751; MPN: DHNF-08F-V; TYPE: CON; Vendor: DIPTRONICS
U2 = 74LVC16373: AGILE_PN: 312-80748; MPN: SN74LVC16373ADGGR; TYPE: IC; Vendor: TI
U4 = FLASH-NOR-64Mx16: AGILE_PN: 342-00562; TYPE: IC; Vendor: Micron
U8-U10 = 74LVC1G86: AGILE_PN: 312-81106; MPN: SN74LVC1G86DCKR; TYPE: IC; Vendor: TI
U107 = FLASH-NAND-BGA: AGILE_PN: 334-77463; TYPE: IC; Vendor: Micron
J2 = SD_CONN: AGILE_PN: 211-79681; MPN: 54-2119-9-R; TYPE: CON; Vendor: Astron
J53 J54 = CONN_1X3: AGILE_PN: 210-75442; MPN: TSW-103-07-F-S; TYPE: HDR; Vendor: Samtec
J57 = CONN_1X1: AGILE_PN: 210-00138; MPN: TSW-101-07-F-S; TYPE: HDR; Vendor: Samtec
Q50 = TRANS_PNP: AGILE_PN: 480-75192; MPN: MMBT3906-7-F; TYPE: TRAN; Vendor: DIODES
R61 R874 R959-R961 R963 R964 R967 R971 R973 = RES: AGILE_PN: 470-75394; TOL: 5%
R865 R866 = RES: AGILE_PN: 470-76089; TOL: 5%
U13 = FLASH-SERIAL-SO16: AGILE_PN: 342-00097; TYPE: IC; Vendor: Micron
U15 = FLASH-SERIAL-SON: BOM_IGNORE: DNP; TYPE: IC; Vendor: Micron
U93 U94 = RClamp0524J: AGILE_PN: 480-77118; TYPE: IC; Vendor: Sentech
D1 = LED: AGILE_PN: 370-76472; MPN: 0603,Green
J3 = CONN_2X8: AGILE_PN: 211-75198; TYPE: HDR; Vendor: Samtec
Q1 Q2 = NMOS: AGILE_PN: 480-78399; MPN: IRLML6346TRPBF; TYPE: MOS; Vendor: IR
R103 = RES: AGILE_PN: 470-80835; TOL: 5%
R104 R105 = RES: AGILE_PN: 470-76480; TOL: 1%
TP1 TP2 = TP: TYPE: PAD
U19 = PCA9546A: AGILE_PN: 312-81105; TYPE: IC; Vendor: NXP
U20 = TXBN0304RSV: AGILE_PN: 312-80668; MPN: TXBN0304RSVR; TYPE: IC; Vendor: TI
U21 U22 = FXLP34P5X: AGILE_PN: 315-80504; TYPE: IC; Vendor: FAIRCHILD
C1287 C1288 = CAP: AGILE_PN: 150-75658; VOLTAGE: 50V
J55 = CONN_1X7: AGILE_PN: 210-00129; MPN: TSW-107-07-F-S; TYPE: HDR; Vendor: Samtec
R969 = RES: AGILE_PN: 470-30454; TOL: 5%
R974 = RES: AGILE_PN: 470-75356; TOL: 1%
U108 = AQ2104: AGILE_PN: 312-81040; ID: 2; MPN: AQR105-B0-EG-Y; TYPE: IC; Vendor: AQUANTIA
U109 = FLASH-SERIAL-SO8: AGILE_PN: 342-00610; MPN: MX25V4006EM1I-13G; TYPE: IC; Vendor: MXIC
Y8 = CRYSTAL_4PIN_v2: AGILE_PN: 230-00038; MPN: 3.2x2.5mm,4pin,CL=12pF,+/-20ppm; TYPE: XTAL
C1290 C1303 C1316 C1337 = CAP: AGILE_PN: 150-76792; VOLTAGE: 4V
C1291 C1294-C1297 C1299-C1301 C1304-C1315 C1317-C1319 C1322-C1327 C1330 C1338-C1344 C1349-C1351 C1359 C1361 = CAP: AGILE_PN: 150-00094; VOLTAGE: 4V
C1292 C1293 C1298 C1321 C1335 C1336 C1348 C1353 = CAP: AGILE_PN: 150-77574; VOLTAGE: 6.3V
C1302 C1320 C1352 C1360 C1362 = CAP: AGILE_PN: 150-79458; VOLTAGE: 6.3V
C1328 C1329 C1331 C1332 C1345 C1346 = CAP: AGILE_PN: 150-75183; VOLTAGE: 25V
FB64 FB65 FB69 = BEAD: AGILE_PN: 180-00041; Vendor: TDK
FB66 = BEAD: AGILE_PN: 180-00042; Vendor: TDK

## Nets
0V85: C1290.2 C1291.2 C1292.1 C1295.2 C1296.2 C1297.2 C1298.1 C1299.2 C1303.2 C1304.2 C1305.2 C1306.2 C1311.2 C1312.2 C1313.2 C1322.2 C1323.2 C1324.2 C1325.2 C1326.2 C1327.2 C1330.2 C1337.2 C1338.2 C1339.2 C1340.2 C1341.2 C1342.2 C1343.2 C1344.2 C1350.2 FB64.2 FB65.2 U108.J6(VDD) U108.J8(VDD) U108.J10(VDD) U108.J12(VDD) U108.K5(VDD) U108.K7(VDD) U108.K9(VDD) U108.K11(VDD) U108.K13(VDD) U108.L6(VDD) U108.L8(VDD) U108.L10(VDD) U108.L12(VDD) U108.M7(VDD) U108.M9(VDD) U108.M11(VDD) U108.M13(VDD) U108.N6(VDD) U108.N8(VDD) U108.N10(VDD) U108.N12(VDD) U108.P5(VDD) U108.P7(VDD) U108.P9(VDD) U108.P11(VDD) U108.P13(VDD) U108.R8(VDD) U108.R10(VDD) U108.R12(VDD) ; also on sheet 19 26
0V85_XGT2_AFE: C1359.1 C1360.1 FB65.1 U108.E10(AFE_DVDD)
0V85_XGT2_VDDSRDS: C1328.1 C1329.1 C1331.1 C1332.1 C1333.1 C1334.1 C1335.1 C1336.1 FB64.1 U108.R5(VDD_SRDS) U108.T8(VDD_SRDS) U108.T10(VDD_SRDS) U108.T12(VDD_SRDS)
1V2: C1293.1 C1300.1 C1301.1 C1302.1 C1308.1 C1309.1 C1310.1 R960.1 R968.1 U108.D4(VA12) U108.D6(VA12) U108.E5(VA12) U108.E7(VA12) U108.E9(VA12) ; also on sheet 10 13 18 19 25
1V8: C23.1 C24.1 C25.1 C26.1 C30.1 C31.1 C32.1 C35.1 C50.1 C53.1 C1274.1 C1275.1 C1276.1 C1277.1 J53.3 R5.2 R6.2 R7.2 R9.2 R10.2 R11.2 R41.2 R42.2 R43.2 R44.2 R47.2 R82.2 R102.2 R797.1 R798.1 R799.1 R800.1 R801.2 R802.2 R803.2 R804.2 R864.1 R952.2 R953.2 U2.7(VCC) U2.18(VCC) U2.31(VCC) U2.42(VCC) U4.29(VIO) U8.5(VCC) U9.5(VCC) U10.5(VCC) U20.13(VCCB) U22.1(VCC1) U107.D3(VCC) U107.G4(VCC) U107.H8(VCC) U107.J6(VCC) ; also on sheet 13 14 22 23 27
1V8_SLP: C52.1 R69.2 R70.2 R81.2 R83.2 R84.2 R85.2 R94.1 R96.1 R98.1 R101.2 R813.2 U21.1(VCC1) ; also on sheet 13 14 22 23 24 26 27
1V8_XGT2_VREGSRDS: C1345.1 C1346.1 C1347.1 C1348.1 U108.T4(P0_VREG_SRDS) U108.T6(P0_VREG_SRDS)
1V35: C1254.1 C1255.1 C1256.1 C1257.1 C1258.1 C1259.1 C1260.1 C1261.1 R1.1 R4.1 ; also on sheet 13 14 27
1V35_SLP: C1.1 C2.1 C3.1 C4.1 C5.1 C6.1 C7.1 C8.1 C9.1 C10.1 C11.1 C12.1 C13.1 C14.1 C998.1 C999.1 C1254.2 C1255.2 C1256.2 C1257.2 C1258.2 C1259.2 C1260.2 C1261.2 J1.51(VDD) J1.54(VDD) J1.57(VDD) J1.60(VDD) J1.62(VDD) J1.65(VDD) J1.66(VDD) J1.69(VDD) J1.72(VDD) J1.75(VDD) J1.78(VDD) J1.170(VDD) J1.173(VDD) J1.176(VDD) J1.179(VDD) J1.182(VDD) J1.183(VDD) J1.186(VDD) J1.189(VDD) J1.191(VDD) J1.194(VDD) J1.197(VDD) R2.1 ; also on sheet 26 27
2V1: C1294.1 C1307.1 C1314.1 C1315.1 C1316.1 C1317.1 C1318.1 C1319.1 C1320.1 C1321.1 FB66.2 FB69.2 U108.A3(VA22) U108.A5(VA22) U108.A7(VA22) U108.A9(VA22) U108.C3(VA22) U108.C5(VA22) U108.C7(VA22) U108.C9(VA22) ; also on sheet 19 25
2V1_XGT2_VDDSRDS: C1349.1 C1351.1 C1352.1 C1353.1 FB69.1 U108.P4(V22_SRDS) U108.R3(V22_SRDS)
2V1_XGT2_XTAL: C1361.1 C1362.1 FB66.1 U108.E18(VA22_XTAL)
2V5: C1289.1 C1354.2 C1355.2 C1356.2 C1357.2 C1358.2 J55.6 R957.2 R958.1 R965.2 R966.2 R970.2 R976.2 U108.E3(VDD_FLASH) U108.J3(VDD_IO) U108.K4(VDD_IO) U108.K16(VDD_IO) U108.L16(VDD_IO) U109.3(~{WP}) U109.7(~{HOLD}) U109.8(VCC) ; also on sheet 10 13 17 18 19 20 27
2V5_SLP: R71.2 R72.2 ; also on sheet 10 13 14 16 26 27
3V3: C33.1 C34.1 C36.1 C37.1 C48.1 C49.1 C51.1 J53.1 Q1.1(G) Q2.1(G) Q50.2(E) R54.2 R55.2 R56.2 R57.2 R65.2 R66.2 R73.2 R74.2 R86.2 R87.2 R88.2 R89.2 R95.2 R97.2 R99.1 R107.1 R108.2 R109.2 R110.1 R111.1 R112.1 R113.1 R114.1 R871.2 R872.2 U4.43(VCC) U13.2(VCC) U15.8(VCC) U19.1(A0) U19.2(A1) U19.13(A2) U19.16(VDD) U20.16(VCCA) U22.5(VCC) ; also on sheet 11 12 13 15 17 21 23 24 27
3V3_SLP: C20.1 C54.1 J1.117(SA0) J1.236(VDDSPD) R90.2 R91.2 U21.5(VCC) ; also on sheet 15 16 22 25 26 27 28
GND: C1.2 C2.2 C3.2 C4.2 C5.2 C6.2 C7.2 C8.2 C9.2 C10.2 C11.2 C12.2 C13.2 C14.2 C15.2 C16.2 C17.2 C18.2 C19.2 C20.2 C21.2 C22.2 C23.2 C24.2 C25.2 C26.2 C30.2 C31.2 C32.2 C33.2 C34.2 C35.2 C36.2 C37.2 C38.2 C39.2 C48.2 C49.2 C50.2 C51.2 C52.2 C53.2 C54.2 C998.2 C999.2 C1274.2 C1275.2 C1276.2 C1277.2 C1287.2 C1288.2 C1289.2 C1290.1 C1291.1 C1292.2 C1293.2 C1294.2 C1295.1 C1296.1 C1297.1 C1298.2 C1299.1 C1300.2 C1301.2 C1302.2 C1303.1 C1304.1 C1305.1 C1306.1 C1307.2 C1308.2 C1309.2 C1310.2 C1311.1 C1312.1 C1313.1 C1314.2 C1315.2 C1316.2 C1317.2 C1318.2 C1319.2 C1320.2 C1321.2 C1322.1 C1323.1 C1324.1 C1325.1 C1326.1 C1327.1 C1328.2 C1329.2 C1330.1 C1331.2 C1332.2 C1333.2 C1334.2 C1335.2 C1336.2 C1337.1 C1338.1 C1339.1 C1340.1 C1341.1 C1342.1 C1343.1 C1344.1 C1345.2 C1346.2 C1347.2 C1348.2 C1349.2 C1350.1 C1351.2 C1352.2 C1353.2 C1354.1 C1355.1 C1356.1 C1357.1 C1358.1 C1359.2 C1360.2 C1361.2 C1362.2 D1.1 J1.2(VSS) J1.5(VSS) J1.8(VSS) J1.11(VSS) J1.14(VSS) J1.17(VSS) J1.20(VSS) J1.23(VSS) J1.26(VSS) J1.29(VSS) J1.32(VSS) J1.35(VSS) J1.38(VSS) J1.41(VSS) J1.44(VSS) J1.47(VSS) J1.80(VSS) J1.83(VSS) J1.86(VSS) J1.89(VSS) J1.92(VSS) J1.95(VSS) J1.98(VSS) J1.101(VSS) J1.104(VSS) J1.107(VSS) J1.110(VSS) J1.113(VSS) J1.116(VSS) J1.119(SA2) J1.121(VSS) J1.124(VSS) J1.127(VSS) J1.130(VSS) J1.133(VSS) J1.136(VSS) J1.139(VSS) J1.142(VSS) J1.145(VSS) J1.148(VSS) J1.151(VSS) J1.154(VSS) J1.157(VSS) J1.160(VSS) J1.163(VSS) J1.166(VSS) J1.199(VSS) J1.202(VSS) J1.205(VSS) J1.208(VSS) J1.211(VSS) J1.214(VSS) J1.217(VSS) J1.220(VSS) J1.223(VSS) J1.226(VSS) J1.229(VSS) J1.232(VSS) J1.235(VSS) J1.237(SA1) J1.239(VSS) J2.3(VSS) J2.6(VSS) J2.12(COM1) J2.13(COM2) J3.12 J3.16 J54.1 J55.7 R3.1 R13.1 R17.2 R19.2 R21.2 R23.2 R25.2 R27.2 R29.2 R31.2 R33.2 R34.2 R35.2 R36.2 R37.2 R38.2 R39.2 R40.2 R104.1 R105.1 R106.1 R955.1 R961.2 R962.2 R963.2 R964.2 R967.2 R972.2 R973.2 R974.1 R975.1 U2.1(~{OE1}) U2.4(GND) U2.10(GND) U2.15(GND) U2.21(GND) U2.24(~{OE2}) U2.26(2D8) U2.27(2D7) U2.28(GND) U2.29(2D6) U2.30(2D5) U2.32(2D4) U2.34(GND) U2.39(GND) U2.45(GND) U4.33(GND) U4.52(GND) U8.3(GND) U9.3(GND) U10.3(GND) U13.10(GND) U15.4(GND) U15.9(EPAD) U19.8(VSS) U20.6(GND) U20.7(GND) U20.8(~{OE}) U21.3(GND) U22.3(GND) U93.9 U94.9 U107.C5(VSS) U107.F7(VSS) U107.K3(VSS) U107.K8(VSS) U108.A1(RG) U108.A18(RG) U108.B3(AVSS) U108.B5(AVSS) U108.B7(AVSS) U108.B9(AVSS) U108.B12(AVSS) U108.B14(AVSS) U108.B16(AVSS) U108.C2(AVSS) U108.C4(AVSS) U108.C6(AVSS) U108.C8(AVSS) U108.C11(AVSS) U108.C13(AVSS) U108.C15(AVSS) U108.C17(AVSS) U108.D3(AVSS) U108.D5(AVSS) U108.D7(AVSS) U108.D9(AVSS) U108.D12(AVSS) U108.D14(AVSS) U108.D16(AVSS) U108.D18(AVSS) U108.E1(DC_MASTER_N) U108.E4(AVSS) U108.E6(AVSS_PLL) U108.E11(AVSS) U108.E13(AVSS) U108.E15(AVSS) U108.E17(AVSS) U108.F6(AVSS) U108.F8(AVSS) U108.F10(AVSS) U108.F12(AVSS) U108.G5(AVSS) U108.G7(AVSS) U108.G9(AVSS) U108.G11(AVSS) U108.H4(MDIO_1P2_SELECT_N) U108.H6(AVSS) U108.H8(AVSS) U108.H10(AVSS) U108.H12(AVSS) U108.J5(VSS) U108.J7(VSS) U108.J9(VSS) U108.J11(VSS) U108.J13(VSS) U108.K6(VSS) U108.K8(VSS) U108.K10(VSS) U108.K12(VSS) U108.L4(RG) U108.L7(VSS) U108.L9(VSS) U108.L11(VSS) U108.L13(VSS) U108.M6(VSS) U108.M8(VSS) U108.M10(VSS) U108.M12(VSS) U108.N1(VSS_SRDS) U108.N2(VSS_SRDS) U108.N5(VSS) U108.N7(VSS) U108.N9(VSS) U108.N11(VSS) U108.N13(VSS) U108.P3(VSS_SRDS) U108.P6(VSS) U108.P8(VSS) U108.P10(VSS) U108.P12(VSS) U108.P17(VSS_SRDS) U108.P18(VSS_SRDS) U108.R1(VSS_SRDS) U108.R2(VSS_SRDS) U108.R4(VSS_SRDS) U108.R6(VSS_SRDS) U108.R7(VSS) U108.R9(VSS) U108.R11(VSS) U108.R13(VSS) U108.R14(VSS_SRDS) U108.T3(VSS_SRDS) U108.T5(VSS_SRDS) U108.T7(VSS_SRDS) U108.T9(VSS_SRDS) U108.T11(VSS_SRDS) U108.T13(VSS_SRDS) U108.T15(VSS_SRDS) U108.U1(VSS_SRDS) U108.U5(VSS_SRDS) U108.U9(VSS_SRDS) U108.U11(VSS_SRDS) U108.U16(VSS_SRDS) U108.U18(VSS_SRDS) U108.V5(VSS_SRDS) U108.V9(VSS_SRDS) U108.V11(VSS_SRDS) U108.V16(VSS_SRDS) U109.4(GND) Y8.2 Y8.4 ; also on sheet 10 11 12 13 14 15 16 17 18 19 20 21 22 23 24 25 26 27 28 29
VDD_SD: C38.1 C39.1 J2.4(VDD) J53.2 R954.1
VDD_SD_SENSE: Q50.3(C) R955.2 ; also on sheet 22
ASLEEP: R101.1 U1.B2(ASLEEP) U21.2(A)
CFG_VBANK0: U10.2(I1) ; also on sheet 22
CFG_VBANK1: U9.2(I1) ; also on sheet 22
CFG_VBANK2: U8.2(I1) ; also on sheet 22
CKSTP_OUT_N: R102.1 U1.F18(~{CKSTP_OUT}) U22.2(A)
COP_CKSTP_OUT_N: J3.15 U22.4(O)
COP_HRESET_N: J3.13 R107.2 ; also on sheet 22
COP_SRESET_N: J3.11 R110.2 ; also on sheet 22
COP_TCK: J3.7 R113.2 U20.3(A3)
COP_TDI: J3.3 R111.2 U20.1(A1)
COP_TDO: J3.1 U20.2(A2)
COP_TMS: J3.9 R114.2 U20.4(A4)
COP_TRST_N: J3.4 R109.1 ; also on sheet 22
CPLD_INT_N: R69.1 U1.F7(IRQ0) ; also on sheet 22
DDR_DQ0: J1.3(DQ0) U1.C21(D1_MDQ00)
DDR_DQ1: J1.4(DQ1) U1.A22(D1_MDQ01)
DDR_DQ2: J1.9(DQ2) U1.A26(D1_MDQ02)
DDR_DQ3: J1.10(DQ3) U1.B26(D1_MDQ03)
DDR_DQ4: J1.122(DQ4) U1.B21(D1_MDQ04)
DDR_DQ5: J1.123(DQ5) U1.A21(D1_MDQ05)
DDR_DQ6: J1.128(DQ6) U1.B24(D1_MDQ06)
DDR_DQ7: J1.129(DQ7) U1.A25(D1_MDQ07)
DDR_DQ8: J1.12(DQ8) U1.C23(D1_MDQ08)
DDR_DQ9: J1.13(DQ9) U1.C24(D1_MDQ09)
DDR_DQ10: J1.18(DQ10) U1.F25(D1_MDQ10)
DDR_DQ11: J1.19(DQ11) U1.F26(D1_MDQ11)
DDR_DQ12: J1.131(DQ12) U1.D22(D1_MDQ12)
DDR_DQ13: J1.132(DQ13) U1.D23(D1_MDQ13)
DDR_DQ14: J1.137(DQ14) U1.B27(D1_MDQ14)
DDR_DQ15: J1.138(DQ15) U1.E25(D1_MDQ15)
DDR_DQ16: J1.21(DQ16) U1.E23(D1_MDQ16)
DDR_DQ17: J1.22(DQ17) U1.E24(D1_MDQ17)
DDR_DQ18: J1.27(DQ18) U1.J23(D1_MDQ18)
DDR_DQ19: J1.28(DQ19) U1.K23(D1_MDQ19)
DDR_DQ20: J1.140(DQ20) U1.F22(D1_MDQ20)
DDR_DQ21: J1.141(DQ21) U1.H22(D1_MDQ21)
DDR_DQ22: J1.146(DQ22) U1.H23(D1_MDQ22)
DDR_DQ23: J1.147(DQ23) U1.J24(D1_MDQ23)
DDR_DQ24: J1.30(DQ24) U1.H26(D1_MDQ24)
DDR_DQ25: J1.31(DQ25) U1.J25(D1_MDQ25)
DDR_DQ26: J1.36(DQ26) U1.P26(D1_MDQ26)
DDR_DQ27: J1.37(DQ27) U1.N25(D1_MDQ27)
DDR_DQ28: J1.149(DQ28) U1.G25(D1_MDQ28)
DDR_DQ29: J1.150(DQ29) U1.H25(D1_MDQ29)
DDR_DQ30: J1.155(DQ30) U1.M26(D1_MDQ30)
DDR_DQ31: J1.156(DQ31) U1.M25(D1_MDQ31)
DDR_DQ32: J1.81(DQ32) U1.T25(D1_MDQ32)
DDR_DQ33: J1.82(DQ33) U1.U25(D1_MDQ33)
DDR_DQ34: J1.87(DQ34) U1.AA26(D1_MDQ34)
DDR_DQ35: J1.88(DQ35) U1.AA25(D1_MDQ35)
DDR_DQ36: J1.200(DQ36) U1.P25(D1_MDQ36)
DDR_DQ37: J1.201(DQ37) U1.R25(D1_MDQ37)
DDR_DQ38: J1.206(DQ38) U1.W26(D1_MDQ38)
DDR_DQ39: J1.207(DQ39) U1.Y25(D1_MDQ39)
DDR_DQ40: J1.90(DQ40) U1.V24(D1_MDQ40)
DDR_DQ41: J1.91(DQ41) U1.W23(D1_MDQ41)
DDR_DQ42: J1.96(DQ42) U1.AA22(D1_MDQ42)
DDR_DQ43: J1.97(DQ43) U1.AC22(D1_MDQ43)
DDR_DQ44: J1.209(DQ44) U1.W22(D1_MDQ44)
DDR_DQ45: J1.210(DQ45) U1.V23(D1_MDQ45)
DDR_DQ46: J1.215(DQ46) U1.AB24(D1_MDQ46)
DDR_DQ47: J1.216(DQ47) U1.AB23(D1_MDQ47)
DDR_DQ48: J1.99(DQ48) U1.AD26(D1_MDQ48)
DDR_DQ49: J1.100(DQ49) U1.AD25(D1_MDQ49)
DDR_DQ50: J1.105(DQ50) U1.AD23(D1_MDQ50)
DDR_DQ51: J1.106(DQ51) U1.AE22(D1_MDQ51)
DDR_DQ52: J1.218(DQ52) U1.AB25(D1_MDQ52)
DDR_DQ53: J1.219(DQ53) U1.AC25(D1_MDQ53)
DDR_DQ54: J1.224(DQ54) U1.AC23(D1_MDQ54)
DDR_DQ55: J1.225(DQ55) U1.AE23(D1_MDQ55)
DDR_DQ56: J1.108(DQ56) U1.AG25(D1_MDQ56)
DDR_DQ57: J1.109(DQ57) U1.AH25(D1_MDQ57)
DDR_DQ58: J1.114(DQ58) U1.AH22(D1_MDQ58)
DDR_DQ59: J1.115(DQ59) U1.AF22(D1_MDQ59)
DDR_DQ60: J1.227(DQ60) U1.AF26(D1_MDQ60)
DDR_DQ61: J1.228(DQ61) U1.AH26(D1_MDQ61)
DDR_DQ62: J1.233(DQ62) U1.AH23(D1_MDQ62)
DDR_DQ63: J1.234(DQ63) U1.AF23(D1_MDQ63)
DDR_ECC0: J1.39(CB0) U1.L24(D1_MECC0)
DDR_ECC1: J1.40(CB1) U1.N23(D1_MECC1)
DDR_ECC2: J1.45(CB2) U1.T23(D1_MECC2)
DDR_ECC3: J1.46(CB3) U1.U23(D1_MECC3)
DDR_ECC4: J1.158(CB4) U1.L23(D1_MECC4)
DDR_ECC5: J1.159(CB5) U1.M23(D1_MECC5)
DDR_ECC6: J1.164(CB6) U1.R24(D1_MECC6)
DDR_ECC7: J1.165(CB7) U1.T24(D1_MECC7)
DDR_MA0: J1.188(A0) U1.V28(D1_MA00)
DDR_MA1: J1.181(A1) U1.N28(D1_MA01)
DDR_MA2: J1.61(A2) U1.N27(D1_MA02)
DDR_MA3: J1.180(A3) U1.M28(D1_MA03)
DDR_MA4: J1.59(A4) U1.L27(D1_MA04)
DDR_MA5: J1.58(A5) U1.L28(D1_MA05)
DDR_MA6: J1.178(A6) U1.K28(D1_MA06)
DDR_MA7: J1.56(A7) U1.J28(D1_MA07)
DDR_MA8: J1.177(A8) U1.J27(D1_MA08)
DDR_MA9: J1.175(A9) U1.G27(D1_MA09)
DDR_MA10: J1.70(A10/AP) U1.Y27(D1_MA10)
DDR_MA11: J1.55(A11) U1.H28(D1_MA11)
DDR_MA12: J1.174(A12/~{BC}) U1.G28(D1_MA12)
DDR_MA13: J1.196(A13) U1.AE28(D1_MA13)
DDR_MA14: J1.172(A14) U1.E27(D1_MA14)
DDR_MA15: J1.171(A15) U1.D28(D1_MA15)
DDR_MAPAR_ERR: J1.53(~{ERROUT}/NC) R4.2 U1.F28(~{D1_MAPAR_ERR})
DDR_MAPAR_OUT: J1.68(PARIN/NC) U1.V27(D1_MAPAR_OUT)
DDR_MBA0: J1.71(BA0) U1.Y28(D1_MBA0)
DDR_MBA1: J1.190(BA1) U1.W28(D1_MBA1)
DDR_MBA2: J1.52(BA2) U1.E28(D1_MBA2)
DDR_MCAS_N: J1.74(~{CAS}) U1.AC28(~{D1_MCAS})
DDR_MCK0_N: J1.185(~{CK0}) U1.T28(~{D1_MCK0})
DDR_MCK0_P: J1.184(CK0) U1.T27(D1_MCK0)
DDR_MCK1_N: J1.64(~{CK1}) U1.R28(~{D1_MCK1})
DDR_MCK1_P: J1.63(CK1) U1.R27(D1_MCK1)
DDR_MCKE0: J1.50(CKE0) U1.C27(D1_MCKE0) ; also on sheet 27
DDR_MCKE1: J1.169(CKE1) U1.C28(D1_MCKE1) ; also on sheet 27
DDR_MCS0_N: J1.193(~{S0}) U1.AB28(~{D1_MCS0})
DDR_MCS1_N: J1.76(~{S1}) U1.AC27(~{D1_MCS1})
DDR_MCS2_N: J1.79(~{S2}/NC) U1.AG27(~{D1_MCS2})
DDR_MCS3_N: J1.198(~{S3}/NC) U1.AF28(~{D1_MCS3})
DDR_MDM0: J1.125(DM0/DQS9) U1.B22(D1_MDM0)
DDR_MDM1: J1.134(DM1/DQS10) U1.C25(D1_MDM1)
DDR_MDM2: J1.143(DM2/DQS11) U1.F23(D1_MDM2)
DDR_MDM3: J1.152(DM3/DQS12) U1.K26(D1_MDM3)
DDR_MDM4: J1.203(DM4/DQS13) U1.U26(D1_MDM4)
DDR_MDM5: J1.212(DM5/DQS14) U1.Y24(D1_MDM5)
DDR_MDM6: J1.221(DM6/DQS15) U1.AD24(D1_MDM6)
DDR_MDM7: J1.230(DM7/DQS16) U1.AF24(D1_MDM7)
DDR_MDM8: J1.161(DM8/DQS17) U1.N24(D1_MDM8)
DDR_MDQS0_N: J1.6(~{DQS0}) U1.A23(~{D1_MDQS0})
DDR_MDQS0_P: J1.7(DQS0) U1.A24(D1_MDQS0)
DDR_MDQS1_N: J1.15(~{DQS1}) U1.D25(~{D1_MDQS1})
DDR_MDQS1_P: J1.16(DQS1) U1.D26(D1_MDQS1)
DDR_MDQS2_N: J1.24(~{DQS2}) U1.G23(~{D1_MDQS2})
DDR_MDQS2_P: J1.25(DQS2) U1.G24(D1_MDQS2)
DDR_MDQS3_N: J1.33(~{DQS3}) U1.K25(~{D1_MDQS3})
DDR_MDQS3_P: J1.34(DQS3) U1.L25(D1_MDQS3)
DDR_MDQS4_N: J1.84(~{DQS4}) U1.V25(~{D1_MDQS4})
DDR_MDQS4_P: J1.85(DQS4) U1.W25(D1_MDQS4)
DDR_MDQS5_N: J1.93(~{DQS5}) U1.Y23(~{D1_MDQS5})
DDR_MDQS5_P: J1.94(DQS5) U1.AA23(D1_MDQS5)
DDR_MDQS6_N: J1.102(~{DQS6}) U1.AF25(~{D1_MDQS6})
DDR_MDQS6_P: J1.103(DQS6) U1.AE25(D1_MDQS6)
DDR_MDQS7_N: J1.111(~{DQS7}) U1.AH24(~{D1_MDQS7})
DDR_MDQS7_P: J1.112(DQS7) U1.AG24(D1_MDQS7)
DDR_MDQS8_N: J1.42(~{DQS8}) U1.P23(~{D1_MDQS8})
DDR_MDQS8_P: J1.43(DQS8) U1.R23(D1_MDQS8)
DDR_MODT0: J1.195(ODT0) U1.AD28(D1_MODT0)
DDR_MODT1: J1.77(ODT1) U1.AE27(D1_MODT1)
DDR_MRAS_N: J1.192(~{RAS}) U1.AA28(~{D1_MRAS})
DDR_MWE_N: J1.73(~{WE}) U1.AB27(~{D1_MWE})
DDR_REFCLK: U1.J21(DDRCLK) ; also on sheet 23
DDR_RST_N: J1.168(~{RESET}) R2.2 ; also on sheet 22
EC1_INT_N: R71.1 U1.AB4(IRQ2) ; also on sheet 16
EC1_PME_N: R72.1 U1.AC5(IRQ3) ; also on sheet 16 22
EC2_INT_N: R73.1 U1.L4(IRQ4) ; also on sheet 17
EC2_PME_N: R74.1 U1.U3(IRQ5) ; also on sheet 17
EMI2_MDC: U108.J18(MDC) ; also on sheet 10 18
EMI2_MDIO: U108.L18(MDIO) ; also on sheet 10 18
EVDD: J57.1 R60.2 R62.2 R63.2 R64.2 R67.2 R68.2 ; also on sheet 13 27
EVT_BRD_ISO: R81.1 U1.A3(~{IRQ_OUT}) ; also on sheet 22
EVT_PWR_EN: R85.1 U1.C1(~{EVT2}) ; also on sheet 22
EVT_PWR_OK: R813.1 U1.C2(~{EVT3}) ; also on sheet 22
HRESET_N: R96.2 U1.E8(~{HRESET}) ; also on sheet 22
I2C1_SCL: Q1.2(S) R89.1 U1.W1(IIC1_SCL) ; also on sheet 15
I2C1_SCL_SLP: J1.118(SCL) Q1.3(D) R91.1 ; also on sheet 15 24 25
I2C1_SDA: Q2.2(S) R88.1 U1.V1(IIC1_SDA) ; also on sheet 15
I2C1_SDA_SLP: J1.238(SDA) Q2.3(D) R90.1 ; also on sheet 15 24 25
I2C2_MPEX1_SCL: U19.5(SC0) ; also on sheet 21
I2C2_MPEX1_SDA: U19.4(SD0) ; also on sheet 21
I2C2_MPEX2_SCL: U19.7(SC1) ; also on sheet 21
I2C2_MPEX2_SDA: U19.6(SD1) ; also on sheet 21
I2C2_PEX_SCL: U19.12(SC3) ; also on sheet 21
I2C2_PEX_SDA: U19.11(SD3) ; also on sheet 21
IFC_A5: R14.2 U10.1(I0)
IFC_A6: R15.2 U9.1(I0)
IFC_A7: R16.2 U8.1(I0)
IFC_A8: R18.2 U4.2(A22)
IFC_A9: R20.2 U4.15(A21)
IFC_A10: R22.2 U4.12(A20)
IFC_A11: R24.2 U4.11(A19)
IFC_A12: R26.2 U4.18(A18)
IFC_A13: R28.2 U4.19(A17)
IFC_A14: R30.2 U4.54(A16)
IFC_A15: R32.2 U4.3(A15)
IFC_A16: R797.2 SW2.5 U1.C5(IFC_A16) U4.4(A14) ; also on sheet 22
IFC_A17: R798.2 SW2.6 U1.C6(IFC_A17) U4.5(A13) ; also on sheet 22
IFC_A18: R799.2 SW2.3 U1.D7(IFC_A18) U4.6(A12) ; also on sheet 22
IFC_A19: R800.2 SW2.4 U1.C7(IFC_A19) U4.7(A11) ; also on sheet 22
IFC_A20: R13.2 R864.2 U1.D8(IFC_A20) U4.8(A10)
IFC_A21: SW2.7 U1.C8(IFC_A21) U4.9(A9) ; also on sheet 22
IFC_A22: U1.D9(IFC_A22) U4.10(A8)
IFC_A23: U1.C9(IFC_A23) U4.20(A7)
IFC_A24: U1.D10(IFC_A24) U4.21(A6)
IFC_A25: U1.C10(IFC_A25) U4.22(A5)
IFC_A26: U1.E11(IFC_A26) U4.23(A4)
IFC_A27: U1.C11(IFC_A27) U4.24(A3) ; also on sheet 22
IFC_A28: U1.D11(IFC_A28) U4.25(A2) ; also on sheet 22
IFC_A29: U1.C12(IFC_A29) U4.26(A1) ; also on sheet 22
IFC_A30: U1.D12(IFC_A30) U4.31(A0) ; also on sheet 22
IFC_A31: U1.E12(IFC_A31) ; also on sheet 22
IFC_AD0: U1.A4(IFC_AD00) U4.51(DQ15/A-1) U107.J8(I/O7) ; also on sheet 22
IFC_AD1: U1.B5(IFC_AD01) U4.49(DQ14) U107.K7(I/O6) ; also on sheet 22
IFC_AD2: U1.A5(IFC_AD02) U4.47(DQ13) U107.J7(I/O5) ; also on sheet 22
IFC_AD3: U1.B6(IFC_AD03) U4.45(DQ12) U107.K6(I/O4) ; also on sheet 22
IFC_AD4: U1.A6(IFC_AD04) U4.42(DQ11) U107.K5(I/O3) ; also on sheet 22
IFC_AD5: U1.A7(IFC_AD05) U2.47(1D1) U4.40(DQ10) U107.K4(I/O2) ; also on sheet 22
IFC_AD6: U1.B8(IFC_AD06) U2.46(1D2) U4.38(DQ9) U107.J4(I/O1) ; also on sheet 22
IFC_AD7: U1.A8(IFC_AD07) U2.44(1D3) U4.36(DQ8) U107.H4(I/O0) ; also on sheet 22
IFC_AD8: SW1.1 U1.B9(IFC_AD08) U2.43(1D4) U4.50(DQ7) ; also on sheet 22
IFC_AD9: SW1.2 U1.A9(IFC_AD09) U2.41(1D5) U4.48(DQ6) ; also on sheet 22
IFC_AD10: SW1.3 U1.A10(IFC_AD10) U2.40(1D6) U4.46(DQ5) ; also on sheet 22
IFC_AD11: SW1.4 U1.B11(IFC_AD11) U2.38(1D7) U4.44(DQ4) ; also on sheet 22
IFC_AD12: SW1.5 U1.A11(IFC_AD12) U2.37(1D8) U4.41(DQ3) ; also on sheet 22
IFC_AD13: SW1.6 U1.B12(IFC_AD13) U2.36(2D1) U4.39(DQ2) ; also on sheet 22
IFC_AD14: SW1.7 U1.A12(IFC_AD14) U2.35(2D2) U4.37(DQ1) ; also on sheet 22
IFC_AD15: SW1.8 U1.A13(IFC_AD15) U2.33(2D3) U4.35(DQ0) ; also on sheet 22
IFC_AVD: R801.1 SW2.8 U1.D17(IFC_AVD) U2.25(LE2) U2.48(LE1) U107.C4(ALE) ; also on sheet 22
IFC_CLE: SW2.1 U1.F16(IFC_CLE) U107.D5(CLE) ; also on sheet 22
IFC_CLK: R12.2 ; also on sheet 22
IFC_CLK_R: R12.1 U1.A17(IFC_CLK0)
IFC_CS0_N: R11.1 U1.C13(~{IFC_CS0}) ; also on sheet 22
IFC_CS1_N: R10.1 U1.E15(~{IFC_CS1}) ; also on sheet 22
IFC_CS2_N: R9.1 U1.D16(~{IFC_CS2}) ; also on sheet 22
IFC_NDWE_N: U1.D14(IFC_NDDDR_CLK) U107.C7(~{WE})
IFC_OE_N: R803.1 U1.D15(~{IFC_OE}) U4.34(~{OE}) U107.D4(~{RE}) ; also on sheet 22
IFC_RB0_N: R7.1 U1.B15(~{IFC_RB0}) ; also on sheet 22
IFC_RB1_N: R6.1 U1.A15(~{IFC_RB1}) ; also on sheet 22
IFC_TE: SW2.2 U1.B14(IFC_TE) ; also on sheet 22
IFC_VA5: U4.55(A25) U10.4(O)
IFC_VA6: U4.56(A24) U9.4(O)
IFC_VA7: U4.1(A23) U8.4(O)
IFC_WE_N: R804.1 U1.D13(~{IFC_WE0}) U4.13(~{WE}) ; also on sheet 22
IFC_WP_N: R802.1 U1.F17(~{IFC_WP0}) U107.C3(~{WP}) ; also on sheet 22
JTAG_TCK: U1.E18(TCK) U20.10(B3)
JTAG_TDI: U1.A18(TDI) U20.12(B1)
JTAG_TDO: U1.C18(TDO) U20.11(B2)
JTAG_TMS: U1.B18(TMS) U20.9(B4)
JTAG_TRST_N: U1.D19(~{TRST}) ; also on sheet 22
MVREF: C21.1 C22.1 U1.F20(D1_MVREF) ; also on sheet 27
MVREF_SLP: C18.1 C19.1 J1.1(VREFDQ) J1.67(VREFCA) ; also on sheet 27
NAND_CS_N: R952.1 U107.C6(~{CE}) ; also on sheet 22
NAND_RB_N: R953.1 U107.C8(R/~{B}) ; also on sheet 22
NOR_CS_N: R43.1 U4.32(~{CE}) ; also on sheet 22
NOR_RB_N: R44.1 U4.17(RDY/~{BUSY}) ; also on sheet 22
NOR_RST_N: R47.1 U4.14(~{RESET}) ; also on sheet 22
PORESET_N: R94.2 U1.F13(~{PORESET}) ; also on sheet 22
RESET_REQ_N: R98.2 U1.B3(~{RESET_REQ}) ; also on sheet 22
SDHC_CD_N: J2.10(~{INSERT}) R66.1 U1.L5(~{SDHC_CD}) U93.4 U93.5
SDHC_CLK: J2.5(CLK/SCLK) R61.2 R68.1 U94.1 U94.8
SDHC_CMD: J2.2(CMD/DIN) R67.1 U1.K3(SDHC_CMD) U93.3 U93.6
SDHC_DAT0: J2.7(D0/DOUT) R60.1 U1.L2(SDHC_DAT0) U94.2 U94.7
SDHC_DAT1: J2.8(D1/RSV) R62.1 U1.K4(SDHC_DAT1) U94.3 U94.6
SDHC_DAT2: J2.9(D2/RSV) R63.1 U1.L3(SDHC_DAT2) U93.1 U93.8
SDHC_DAT3: J2.1(D3/~{CS}) R64.1 U1.L1(SDHC_DAT3) U93.2 U93.7
SDHC_VS: R874.1 ; also on sheet 14 22
SDHC_WP: J2.11(~{PROTECT}) R65.1 U1.M5(SDHC_WP) U94.4 U94.5
SGMII_RX_N: U108.V6(TX_LN2_N) ; also on sheet 21
SGMII_RX_P: U108.U6(TX_LN2_P) ; also on sheet 21
SGMII_TX_N: C1285.1 ; also on sheet 21
SGMII_TX_P: C1286.1 ; also on sheet 21
SPI_CLK: R59.2 R865.1 ; also on sheet 11
SPI_CS0_N: R56.1 U1.M1(~{SPI_CS0}) U13.7(~{CS}) U15.1(~{CS})
SPI_MISO: R54.1 R58.1 U1.P1(SPI_MISO) ; also on sheet 11
SPI_MOSI: R866.1 U1.P2(SPI_MOSI) ; also on sheet 11
SYS_REFCLK: U1.G15(SYSCLK) ; also on sheet 23
SYS_REFCLK_N: U1.F14(~{DIFF_SYSCLK}) ; also on sheet 24
SYS_REFCLK_P: U1.G14(DIFF_SYSCLK) ; also on sheet 24
TDMR_SPI_CS0_N: R872.1 U1.M2(~{SPI_CS1}) ; also on sheet 11
TDMR_SPI_CS1_N: R871.1 U1.M3(~{SPI_CS2}) ; also on sheet 11
TEMP_DIODE_N: U1.G21(TD1_CATHODE) ; also on sheet 15
TEMP_DIODE_P: U1.E21(TD1_ANODE) ; also on sheet 15
TEST_SEL_N: R83.1 U1.G8(~{TEST_SEL}) ; also on sheet 22
UART1_CTS_N: U1.Y2(~{UART1_CTS}) ; also on sheet 15
UART1_RTS_N: U1.Y1(~{UART1_RTS}) ; also on sheet 15
UART1_RXD: U1.AA1(UART1_SIN) ; also on sheet 15
UART1_TXD: U1.AA2(UART1_SOUT) ; also on sheet 15
UART2_CTS_N: U1.Y4(~{UART2_CTS}) ; also on sheet 15
UART2_RTS_N: U1.V4(~{UART2_RTS}) ; also on sheet 15
UART2_RXD: U1.W4(UART2_SIN) ; also on sheet 15
UART2_TXD: U1.AA4(UART2_SOUT) ; also on sheet 15
USB_REFCLK: R873.1 ; also on sheet 14 23
VTT: C15.1 C16.1 C17.1 J1.48(VTT/NC) J1.49(VTT/NC) J1.120(VTT) J1.240(VTT) ; also on sheet 27
XGT2_CM_N: U108.D8(CM_N) ; also on sheet 20
XGT2_CM_P: U108.E8(CM_P) ; also on sheet 20
XGT2_INT_N: R957.1 R959.2 ; also on sheet 22
XGT2_LED_GRN: U108.K1(LED0) ; also on sheet 20
XGT2_LED_YEL: U108.L1(LED1) ; also on sheet 20
XGT2_MDI0_N: U108.A2(A_N) ; also on sheet 20
XGT2_MDI0_P: U108.B2(A_P) ; also on sheet 20
XGT2_MDI1_N: U108.A4(B_N) ; also on sheet 20
XGT2_MDI1_P: U108.B4(B_P) ; also on sheet 20
XGT2_MDI2_N: U108.A6(C_N) ; also on sheet 20
XGT2_MDI2_P: U108.B6(C_P) ; also on sheet 20
XGT2_MDI3_N: U108.A8(D_N) ; also on sheet 20
XGT2_MDI3_P: U108.B8(D_P) ; also on sheet 20
XGT2_RST_N: R969.1 ; also on sheet 22
XGT2_SPI_CS_N: R976.1 U108.G2(CE_N) U109.1(~{CS})
XGT2_SPI_SCLK: U108.G1(SCLK) U109.6(SCK)
XGT2_SPI_SDI: U108.F2(SOUT) U109.5(SI)
XGT2_SPI_SDO: U108.F1(SIN) U109.2(SO)
XGT2_TCK: J55.3 U108.K14(TCK)
XGT2_TDI: J55.1 U108.L14(TDI)
XGT2_TDO: J55.5 U108.L15(TDO)
XGT2_TMS: J55.2 U108.M16(TMS)
XGT2_TRST_N: J55.4 R975.2 U108.M15(TRST_N)
N16747459: R1.2 U1.U28(D1_MDIC1)
N16747463: R3.2 U1.P28(D1_MDIC0)
N16800565: R42.1 U4.53(~{BYTE})
N16800570: R41.1 U4.16(~{WP}/ACC)
N16821816: R5.1 U1.E14(~{IFC_PERR})
N16864329: R58.2 U13.8(SO) U15.2(SO)
N16864338: R55.1 R866.2 U13.15(SI) U15.5(SI)
N16864354: R865.2 U13.16(SCK) U15.6(SCK)
N16864378: R57.1 U13.1(~{HOLD}) U13.9(~{WP}) U15.3(~{WP}) U15.7(~{HOLD})
N17040696: R59.1 U1.N1(SPI_CLK)
N17040868: R61.1 U1.K1(SDHC_CLK)
N17072443: R106.2 TP2.1(TP) U1.B17(RTC)
N17109221: R95.1 U1.AA3(IIC4_SCL)
N17109223: R97.1 U1.AB3(IIC4_SDA)
N17109295: R87.1 U1.V3(IIC2_SCL) U19.14(SCL)
N17109336: R86.1 U1.Y3(IIC2_SDA) U19.15(SDA)
N17112712: R99.2 U19.3(~{RESET})
N17112758: R104.2 U1.C20(FA_ANALOG_G_V)
N17112821: R105.2 U1.B20(FA_ANALOG_PIN)
N17112937: R84.1 U1.F9(~{SCAN_MODE})
N17116912: R70.1 R873.2 R874.2 U1.D3(IRQ1)
N17271631: R82.1 U1.F19(~{TMP_DETECT})
N17321001: R103.1 U21.4(O)
N17321019: D1.2 R103.2
N17423481: J3.5 R112.2
N17423546: J3.6 R108.1
N17736577: R17.1 SW1.16
N17736598: R19.1 SW1.15
N17736619: R21.1 SW1.14
N17736629: R23.1 SW1.13
N17736659: R25.1 SW1.12
N17736669: R27.1 SW1.11
N17736681: R29.1 SW1.10
N17736695: R31.1 SW1.9
N17736739: R33.1 SW2.16
N17736751: R34.1 SW2.15
N17736763: R35.1 SW2.14
N17736781: R36.1 SW2.13
N17736801: R39.1 SW2.11
N17736803: R37.1 SW2.12
N17736817: R38.1 SW2.10
N17736835: R40.1 SW2.9
N20516568: TP1.1(TP) U1.E6(CLK_OUT)
N22257590: R14.1 U2.2(1Q1)
N22257592: R15.1 U2.3(1Q2)
N22257594: R16.1 U2.5(1Q3)
N22258098: R20.1 U2.8(1Q5)
N22258100: R22.1 U2.9(1Q6)
N22258102: R24.1 U2.11(1Q7)
N22258104: R26.1 U2.12(1Q8)
N22258216: R18.1 U2.6(1Q4)
N22258634: R28.1 U2.13(2Q1)
N22258636: R30.1 U2.14(2Q2)
N22258638: R32.1 U2.16(2Q3)
N23647021: Q50.1(B) R954.2
N23886478: C1285.2 U108.V4(RX_LN2_N)
N23886479: C1286.2 U108.U4(RX_LN2_P)
N23886494: R959.1 U108.K18(INT_N)
N23886496: R970.1 U108.H3(RST_OUT_N)
N23886499: R974.2 U108.A10(RREF_BG)
N23886523: C1287.1 R971.1 Y8.1
N23886526: C1288.1 U108.F18(XTAL_I) Y8.3
N23886535: R971.2 U108.G18(XTAL_O)
N23886543: R958.2 U108.N17(RX_DC_RST_N)
N23886546: R962.1 U108.J15(ADDR1)
N23886548: R967.1 U108.G17(ADDR4)
N23886549: R964.1 U108.H16(ADDR3)
N23886551: R963.1 U108.J16(ADDR2)
N23886557: R961.1 U108.K15(ADDR0)
N23886561: R968.2 R969.2 U108.J4(RST_N)
N23886562: R973.1 U108.F17(XTAL_SELECT_N)
N23886563: R972.1 U108.G13(50M_CLK_TERM)
N23886575: R960.2 U108.F5(TX_EN)
N23886602: J54.3 R965.1 U108.H17(SMB_CLK)
N23886603: J54.2 R966.1 U108.H18(SMB_DAT)

Not connected (* = marked no-connect by the designer): J1 126(NC/~{DQS9})* 135(NC/~{DQS10})* 144(NC/~{DQS11})* 153(NC/~{DQS12})* 162(NC/~{DQS17})* 167(TEST/NC)* 187(~{EVENT}/NC)* 204(NC/~{DQS13})* 213(NC/~{DQS14})* 222(NC/~{DQS15})* 231(NC/~{DQS16})*; J3 2* 8* 10* 14*; U1 A14(IFC_BCTL)* A16(IFC_NDDQS)* A19(IFC_CLK1)* C3(~{EVT4})* C4(~{EVT1})* C14(IFC_PAR1)* C15(IFC_PAR0)* C16(~{IFC_CS3})* D6(~{EVT0})* J20(D1_TPA)* N3(~{SPI_CS3})*; U2 17(2Q4)* 19(2Q5)* 20(2Q6)* 22(2Q7)* 23(2Q8)*; U4 27(NC1)* 28(NC2)* 30(NC3)*; U13 3(NC1)* 4(NC2)* 5(NC3)* 6(NC4)* 11(NC5)* 12(NC6)* 13(NC7)* 14(NC8)*; U19 9(SD2)* 10(SC2)*; U20 5(NC1)* 14(NC2)* 15(NC3)*; U107 A1(NC23)* A2(NC24)* A9(NC26)* A10(NC27)* B1(NC25)* B9(NC28)* B10(NC29)* D6(NC5)* D7(NC6)* D8(NC7)* E3(NC8)* E4(NC9)* E5(NC10)* E6(NC11)* E7(NC12)* E8(NC13)* F3(NC14)* F4(NC15)* F5(NC16)* F6(NC17)* F8(NC18)* G3(DNU1)* G5(LOCK)* G6(NC19)* G7(NC20)* G8(DNU2)* H3(NC21)* H5(NC22)* H6(NC1)* H7(NC2)* J3(NC3)* J5(NC4)* L1(NC30)* L2(NC31)* L9(NC34)* L10(NC35)* M1(NC32)* M2(NC33)* M9(NC36)* M10(NC37)*; U108 A11(NC1)* A12(NC2)* A13(NC3)* A14(NC4)* A15(NC5)* A16(NC6)* A17(NC7)* B1(RNC)* B10(NC8)* B11(NC9)* B13(NC10)* B15(NC11)* B17(NC12)* B18(NC13)* C1(CLK_1588_N)* C10(RNC)* C12(NC14)* C14(NC15)* C16(NC16)* C18(NC17)* D1(CLK_1588_P)* D2(CLKO_50M_A)* D10(RNC)* D11(NC18)* D13(NC19)* D15(NC20)* D17(NC21)* E2(RNC)* E12(NC22)* E14(NC23)* E16(NC24)* F3(TDIO_N)* F4(RNC)* F7(NC25)* F9(NC26)* F11(NC27)* F13(RNC)* F14(NC28)* F15(RNC)* F16(RNC)* G3(TDIO_P)* G4(RNC)* G6(NC29)* G8(NC30)* G10(NC31)* G12(NC32)* G14(RNC)* G15(NC33)* G16(RNC)* H1(RX_DC_DATA)* H2(TX_DC_RST_N)* H5(NC34)* H7(NC35)* H9(NC36)* H11(NC37)* H13(NC38)* H14(RNC)* H15(RNC)* J1(RX_DC_CLK)* J2(RX_DC_SOF)* J14(RNC)* J17(NC39)* K2(NC40)* K3(WAKE)* K17(NC41)* L2(NC42)* L3(PERST_N)* L5(RNC)* L17(NC43)* M1(LED2)* M2(NC44)* M3(NC45)* M4(RNC)* M5(RNC)* M14(RNC)* M17(TX_DC_DATA)* M18(TX_DC_SOF)* N3(NC46)* N4(RNC)* N14(RNC)* N15(1588_SYNC)* N16(RNC)* N18(TX_DC_CLK)* P1(RX_LN0_N)* P2(RX_LN0_P)* P14(RNC)* P15(NC47)* P16(RNC)* R15(NC48)* R16(NC49)* R17(NC50)* R18(NC51)* T1(TX_LN0_N)* T2(TX_LN0_P)* T14(RNC)* T16(NC52)* T17(NC53)* T18(NC54)* U2(RX_LN1_P)* U3(TX_LN1_P)* U7(RX_LN3_P)* U8(TX_LN3_P)* U10(NC55)* U12(NC56)* U13(NC57)* U14(NC58)* U15(NC59)* U17(NC60)* V1(RNC)* V2(RX_LN1_N)* V3(TX_LN1_N)* V7(RX_LN3_N)* V8(TX_LN3_N)* V10(NC61)* V12(NC62)* V13(NC63)* V14(NC64)* V15(NC65)* V17(NC66)* V18(RNC)*

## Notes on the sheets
sheet 1
- 2.5G BASE-T PHY 2 AQR105 POWER SUPPLY
sheet 2
- 2.5G BASE-T PHY 2 AQR105
- LANE2 USED AS 2.5G SGMII MODE TO MAC
- 100 ohms
  DIFF PAIRs
- 100 ohms
  DIFF PAIRs
- PHY ADDR = 0x02
- DC_MASTER_N = 0
- (Daisy Chain Master)
- MDIO_1P2_SELECT_N = 0
- (MDIO Voltage 1.2V)
- Wake-On-LAN unused
- DEBUG HEADER
- Select Crystal
- 100 ohms
  DIFF PAIRs
- Boundry scan use only
sheet 3
- T1024RDB
- Page  Description
- Version Control
- 1
- SCHEMATIC PAGE LISTING
- Version
- Date
- Modifications
- 2
- SYSTEM BLOCK DIAGRAM
- 3
- T1024 DDR3L MEMORY INTERFACE
- V0.1
- 2014/08
- First release of Schematics
- 4
- T1024 IFC INTERFACE
- 5
- T1024 NOR and NAND FLASH INTERFACE
- V1.0
- 2014/08
- Released to Manufacturing
- 6
- T1024 SPI FLASH and SDHC INTERFACE
- 1. Change AQ2104 to AQR105, add another AQR105 for 2.5G SGMII
- 7
- T1024 SYSTEM LOGIC INTERFACE
- V2.0
- 2014/09
- 2. Add serdes mux for PCIe and 2.5G SGMII
- 3. Add VCORE power measurement
- 8
- T1024 ETHERNET and SERDES INTERFACE
- 9
- T1024 QE INTERFACE
- V3.0
- 2014/11
- 1. Add 2 clock mux for SD1/2_REFCLK selection
- 2. Change T1040 debug version resistors "V40" to "DNP"
- 10
- T1024 USB INTERFACE
- 11
- T1024 POWER SUPPLY
- 12
- T1024 PLL FILTERs and GROUND
- 13
- T1024 DUART and I2C DEVICE INTERFACE
- 14
- RGMII ETHERNET PORT 1
- 15
- RGMII ETHERNET PORT 2
- 16
- 10G BASE-T PHY 1 AQR105
- 17
- 10G BASE-T PHY 1 AQR105 POWER SUPPLY
- 18
- 2.5G BASE-T PHY 2 AQR105
- 19
- 2.5G/2.5G BASE-T PHY 2 AQR105 POWER SUPPLY
- 20
- 10G BASE-T RJ46 CONNECTORs
- 21
- PCIe X1 SLOT and MINI PCIe CONNECTORs
- 22
- CPLD
- 23
- SYSTEM CLOCK GENERATORs
- 24
- SYSTEM CLOCK GENERATORs (cont.)
- 25
- T1024 CORE POWER CONVERTOR and SYSTEM POWER CONVERTORs
- 26
- SYSTEM POWER CONVERTORs
- 27
- SYSTEM POWER SWITCHs
- 28
- SYSTEM POWER INPUT
- 29
- MECHANICALs
- 30
- CHANGE LIST
- All information is subject to change without notice.
  No warranty, expressed or applied, is made as to the
  accuracy of the information contained herein. This
  schematic is provided for reference purposes only.
  Contact your Freescale representative to obtain the
  latest information on this product.
sheet 4
- SYSTEM BLOCK DIAGRAM
- RJ45 2x1
- RJ45
- RS232
- RS232 XCVR
- UART1
- DDR3L
- DDR3L UDIMM
- ATX Power
- I2C1
- 72bit, 4GB
- 12V
- RS232
- UART2
- 5V
- RJ45
- RS232 XCVR
- IFC
- NOR FLASH
- 16bit, 128MB
- 0.85V
- VCORE
- USB1
- I2C EEPROM
- 1.0V
- USB Conn.
- USB1
- USB Protect &
  Power Switch
- USB2
- AT24C256
- 1.2V
- Power
  Regulators
- TypeA x2
- USB2
- USB CTL
- NAND FLASH
- 1.35V
- 8bit, 1GB
- 1.5V
- Thermal Monitor
- ADT7461
- 1.8V
- 2.1V
- RGMII
- 2.5V
- MDI
- MDI
- RGMII PHY
- ALTERA CPLD
- 3.3V
- RJ45 2x1
- RJ45
- Magnetics
- RTL8211E-VB
- EMI1
- EPM570G
- SPI
- SPI FLASH
- 5V
- 64MB
- 12V
- MDI
- MDI
- RGMII PHY
- RGMII
- RJ45
- Magnetics
- RTL8211E-VB
- T1024
- SDHC
- SDHC
- SD Card
- Protect
- SDHC/SDXC
- XFI
- JTAG
- JTAG
- RJ46
- Magnetics
- MDI
- Dual 10G Base-T PHY
- EMI2
- OVDD<->3.3V
- COP Conn.
- AQR105
- PCIe
- I2C2CH1
- Mini PCIe Conn.
- RJ46
- Magnetics
- MDI
- Dual 10G Base-T PHY
- 2.5G SGMII
- EMI2
- AQR105
- MUX
- PCIe
- I2C2CH2
- Mini PCIe Conn.
- PCIe
- PEX x1 SLOT
- I2C2CH4
- QE
- SPI
- TDM Riser Card Conn.
sheet 5
- T1024 DDR3L MEMORY INTERFACE
- 1.35V DDR3L SDRAM UDIMM
- 4GB (x72, ECC, DR)
- Micron MPN(4GB,1600): MT18KSF51272AZ-1G6
- T1024: 162 ohm
- SPD ADDR = 0x51
sheet 6
- T1024 IFC INTERFACE
- CS0: NOR or NAND
- CS1: NAND or NOR
- CS2: CPLD
- cfg_test_port_dis
- T1024 RESET CONFIGURATION
- cfg_rcw_src[0:8]
- 0_0010_0111: NOR FLASH BOOT
- 0_0100_0000: SD CARD BOOT
- 0_0100_0101: SPI BOOT
- 1_0001_1001: NAND FLASH BOOT
- cfg_rcw_src0
- cfg_rcw_src1
- cfg_rcw_src2
- cfg_rcw_src3
- cfg_rcw_src4
- cfg_rcw_src5
- cfg_rcw_src6
- cfg_rcw_src7
- cfg_rcw_src8
- cfg_ifc_te
- cfg_pll_config_sel_b
- 1: TE logic 0
- cfg_por_ainit
- cfg_svr0
- cfg_svr1
- cfg_dram_type
- 1: DDR3L
- cfg_rsp_dis
sheet 7
- T1024 NOR and NAND FLASH INTERFACE
- 128MB 16-BIT NOR FLASH
- 1GB 8-BIT NAND FLASH
sheet 8
- T1024 SPI FLASH and SDHC INTERFACE
- 64MB SERIAL FLASH
- EVDD CAN BE 3.3V or 1.8V
- CO-LAYOUT
- SD CARD VDD MANUAL SELECTION
sheet 9
- T1024 SYSTEM LOGIC INTERFACE
- TEST_SEL_B
- FOR T1024, PULL-UP
- cfg_test_port_mux_sel
- XVDD use 1.35V
- I2C ADDR = 0x77
- cfg_xvdd_sel
- LABEL = ASLEEP
